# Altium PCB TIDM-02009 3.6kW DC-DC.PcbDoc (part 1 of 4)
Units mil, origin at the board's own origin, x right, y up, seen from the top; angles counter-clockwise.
Board outline 11220.47 x 8463 mil, 4 copper layers (Top Layer, Signal Layer 1, Signal Layer 2, Bottom Layer), stack 109.77 mil thick; 298 components, 250 nets, 959 pads, 2937 vias.
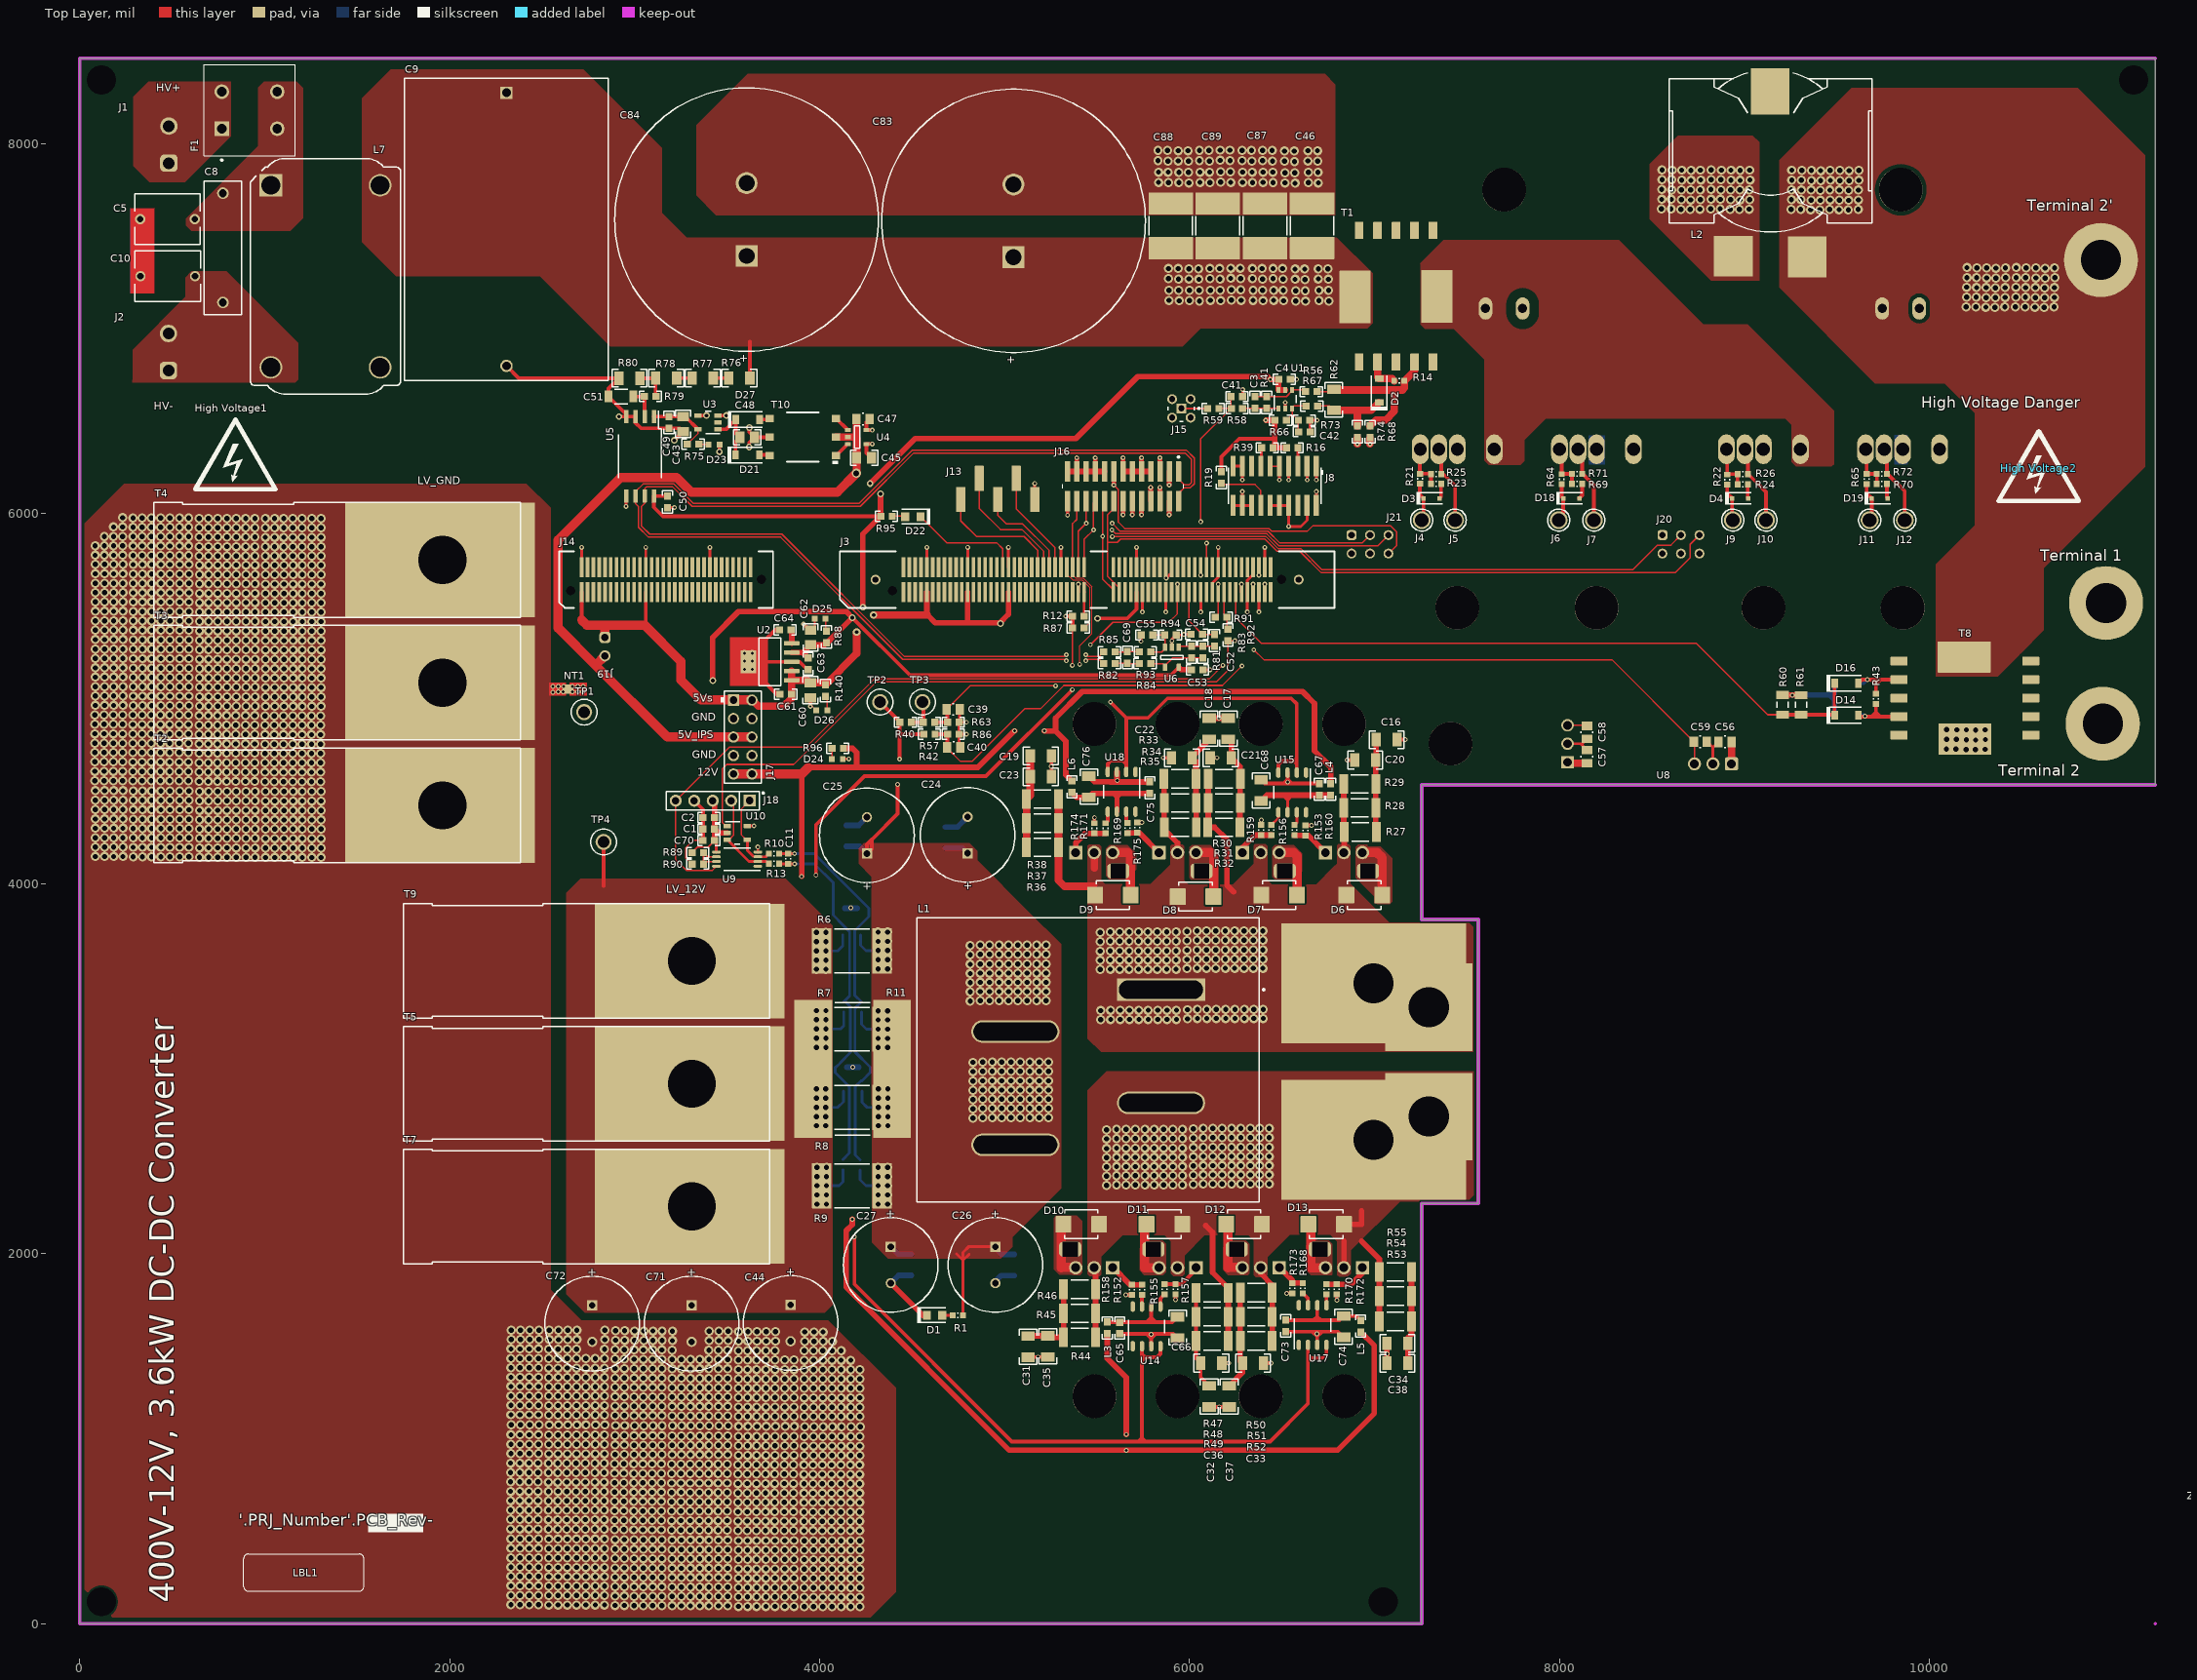
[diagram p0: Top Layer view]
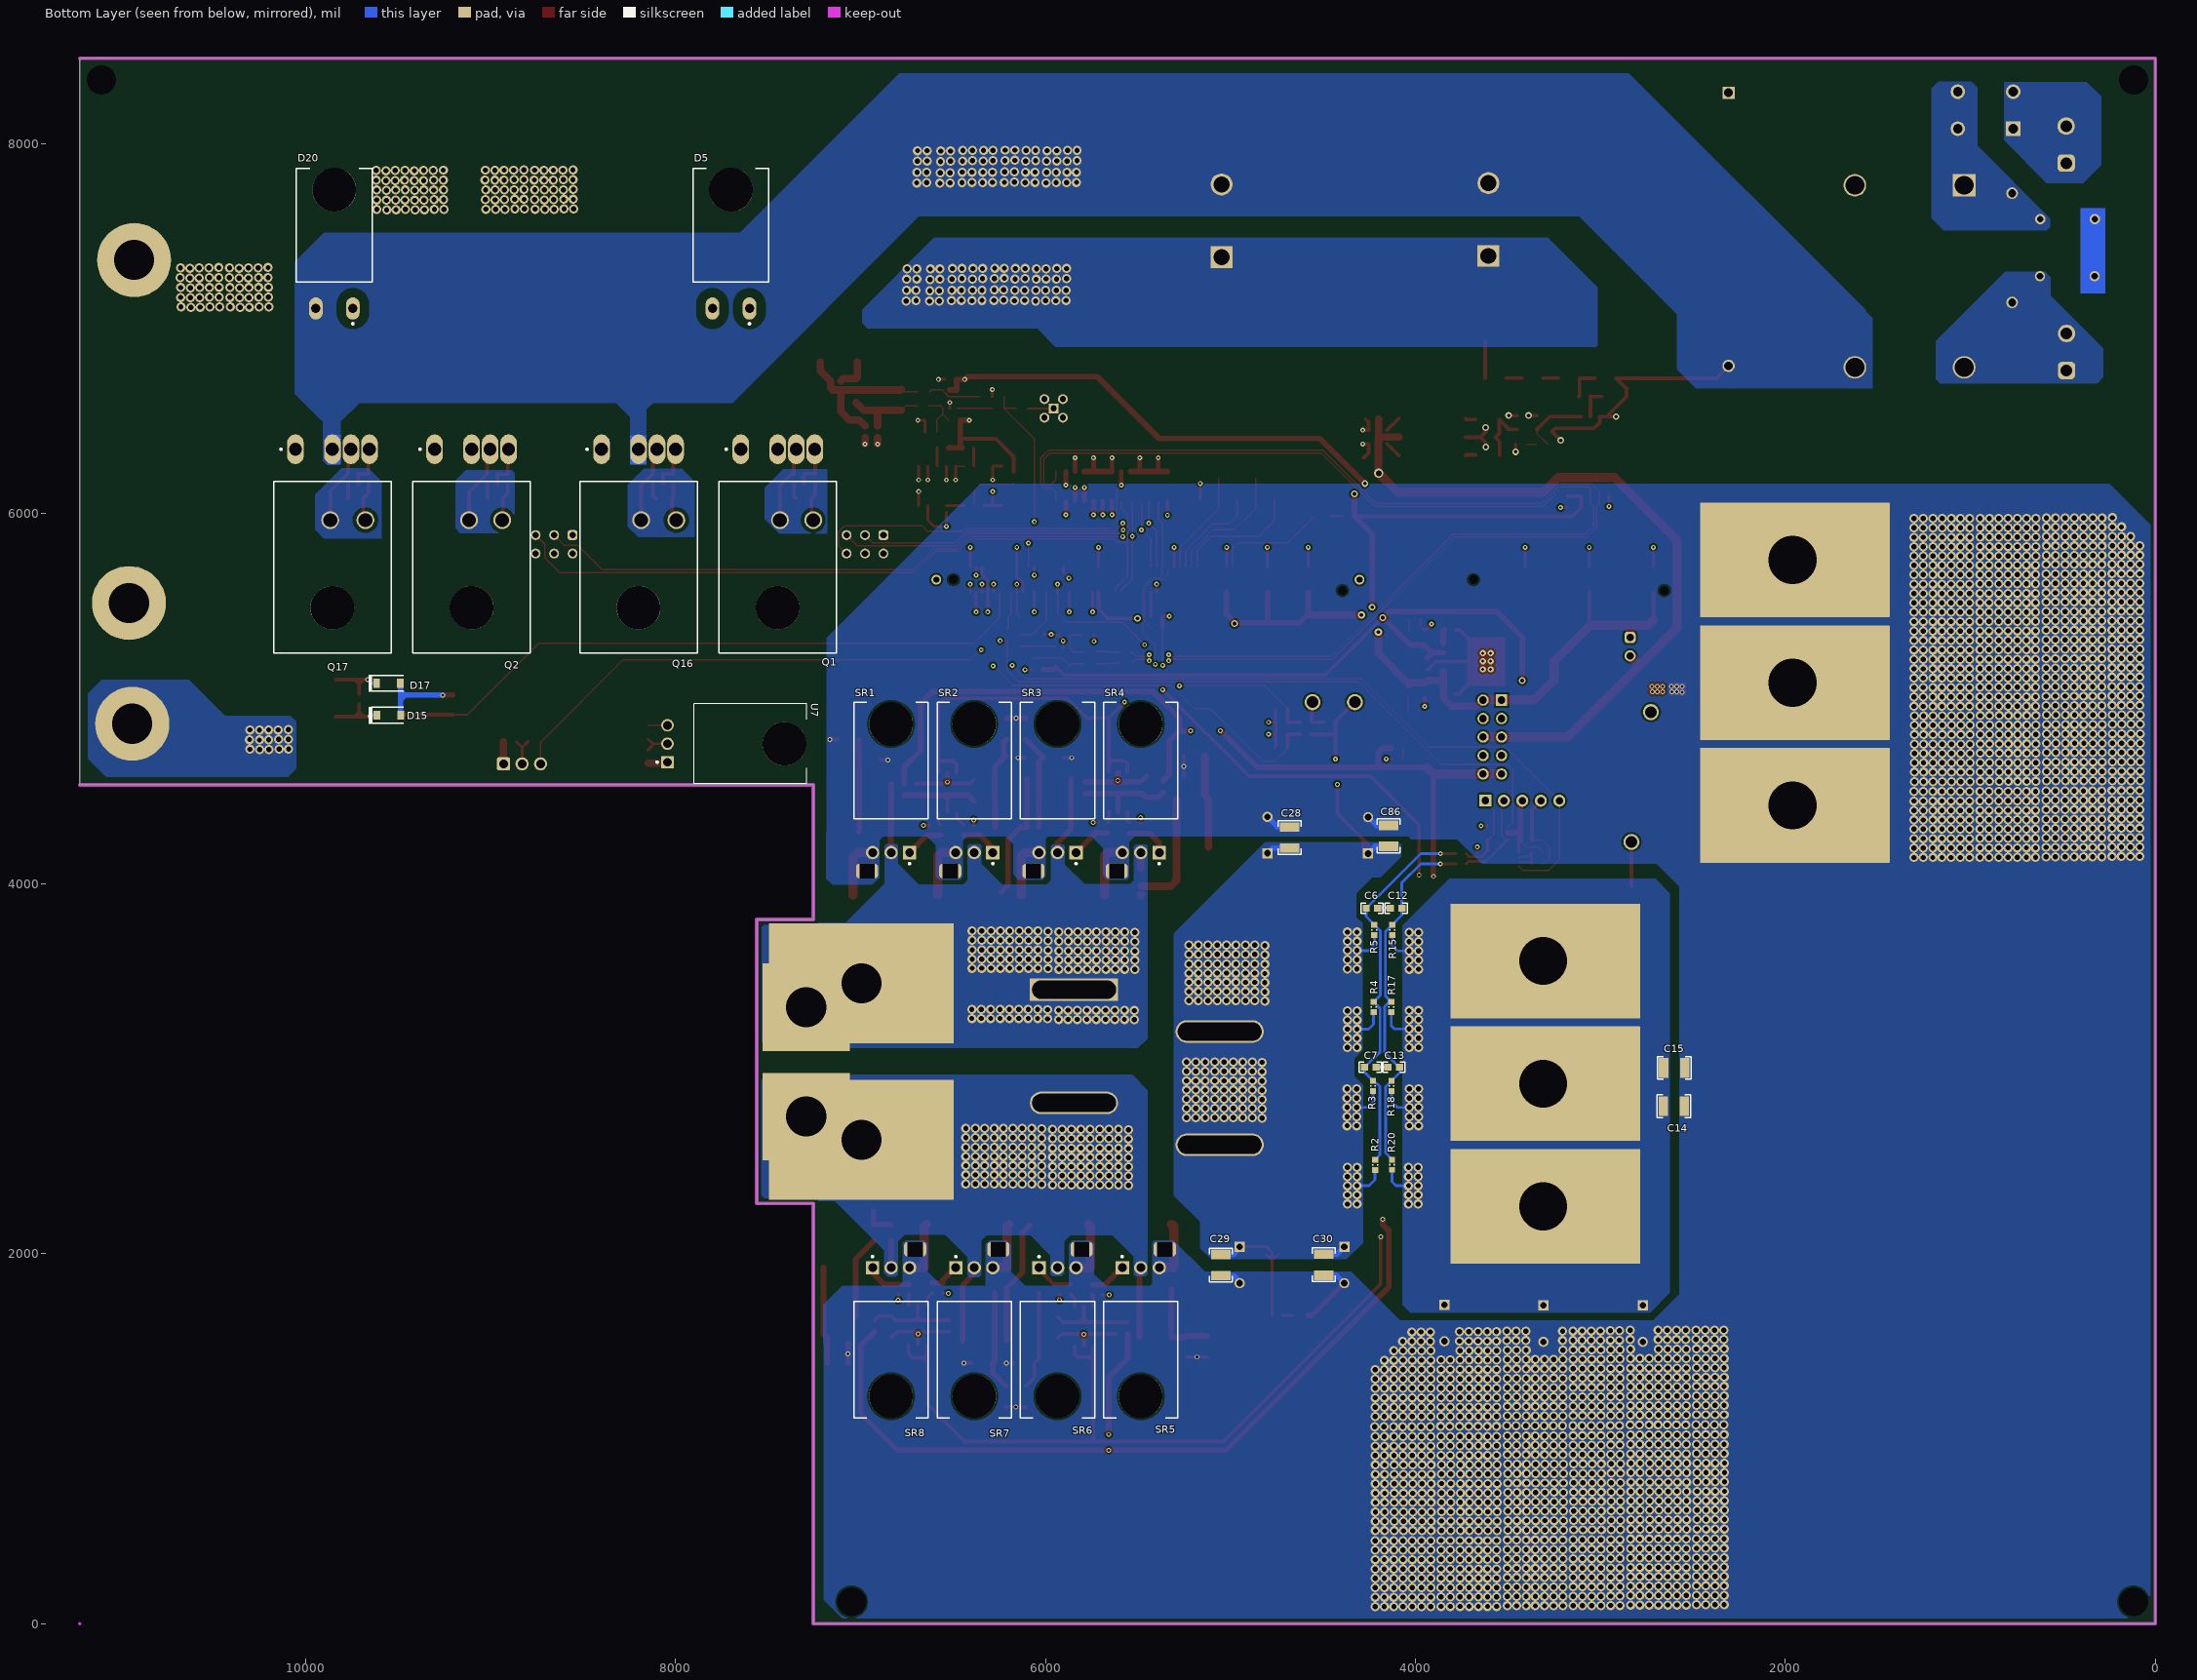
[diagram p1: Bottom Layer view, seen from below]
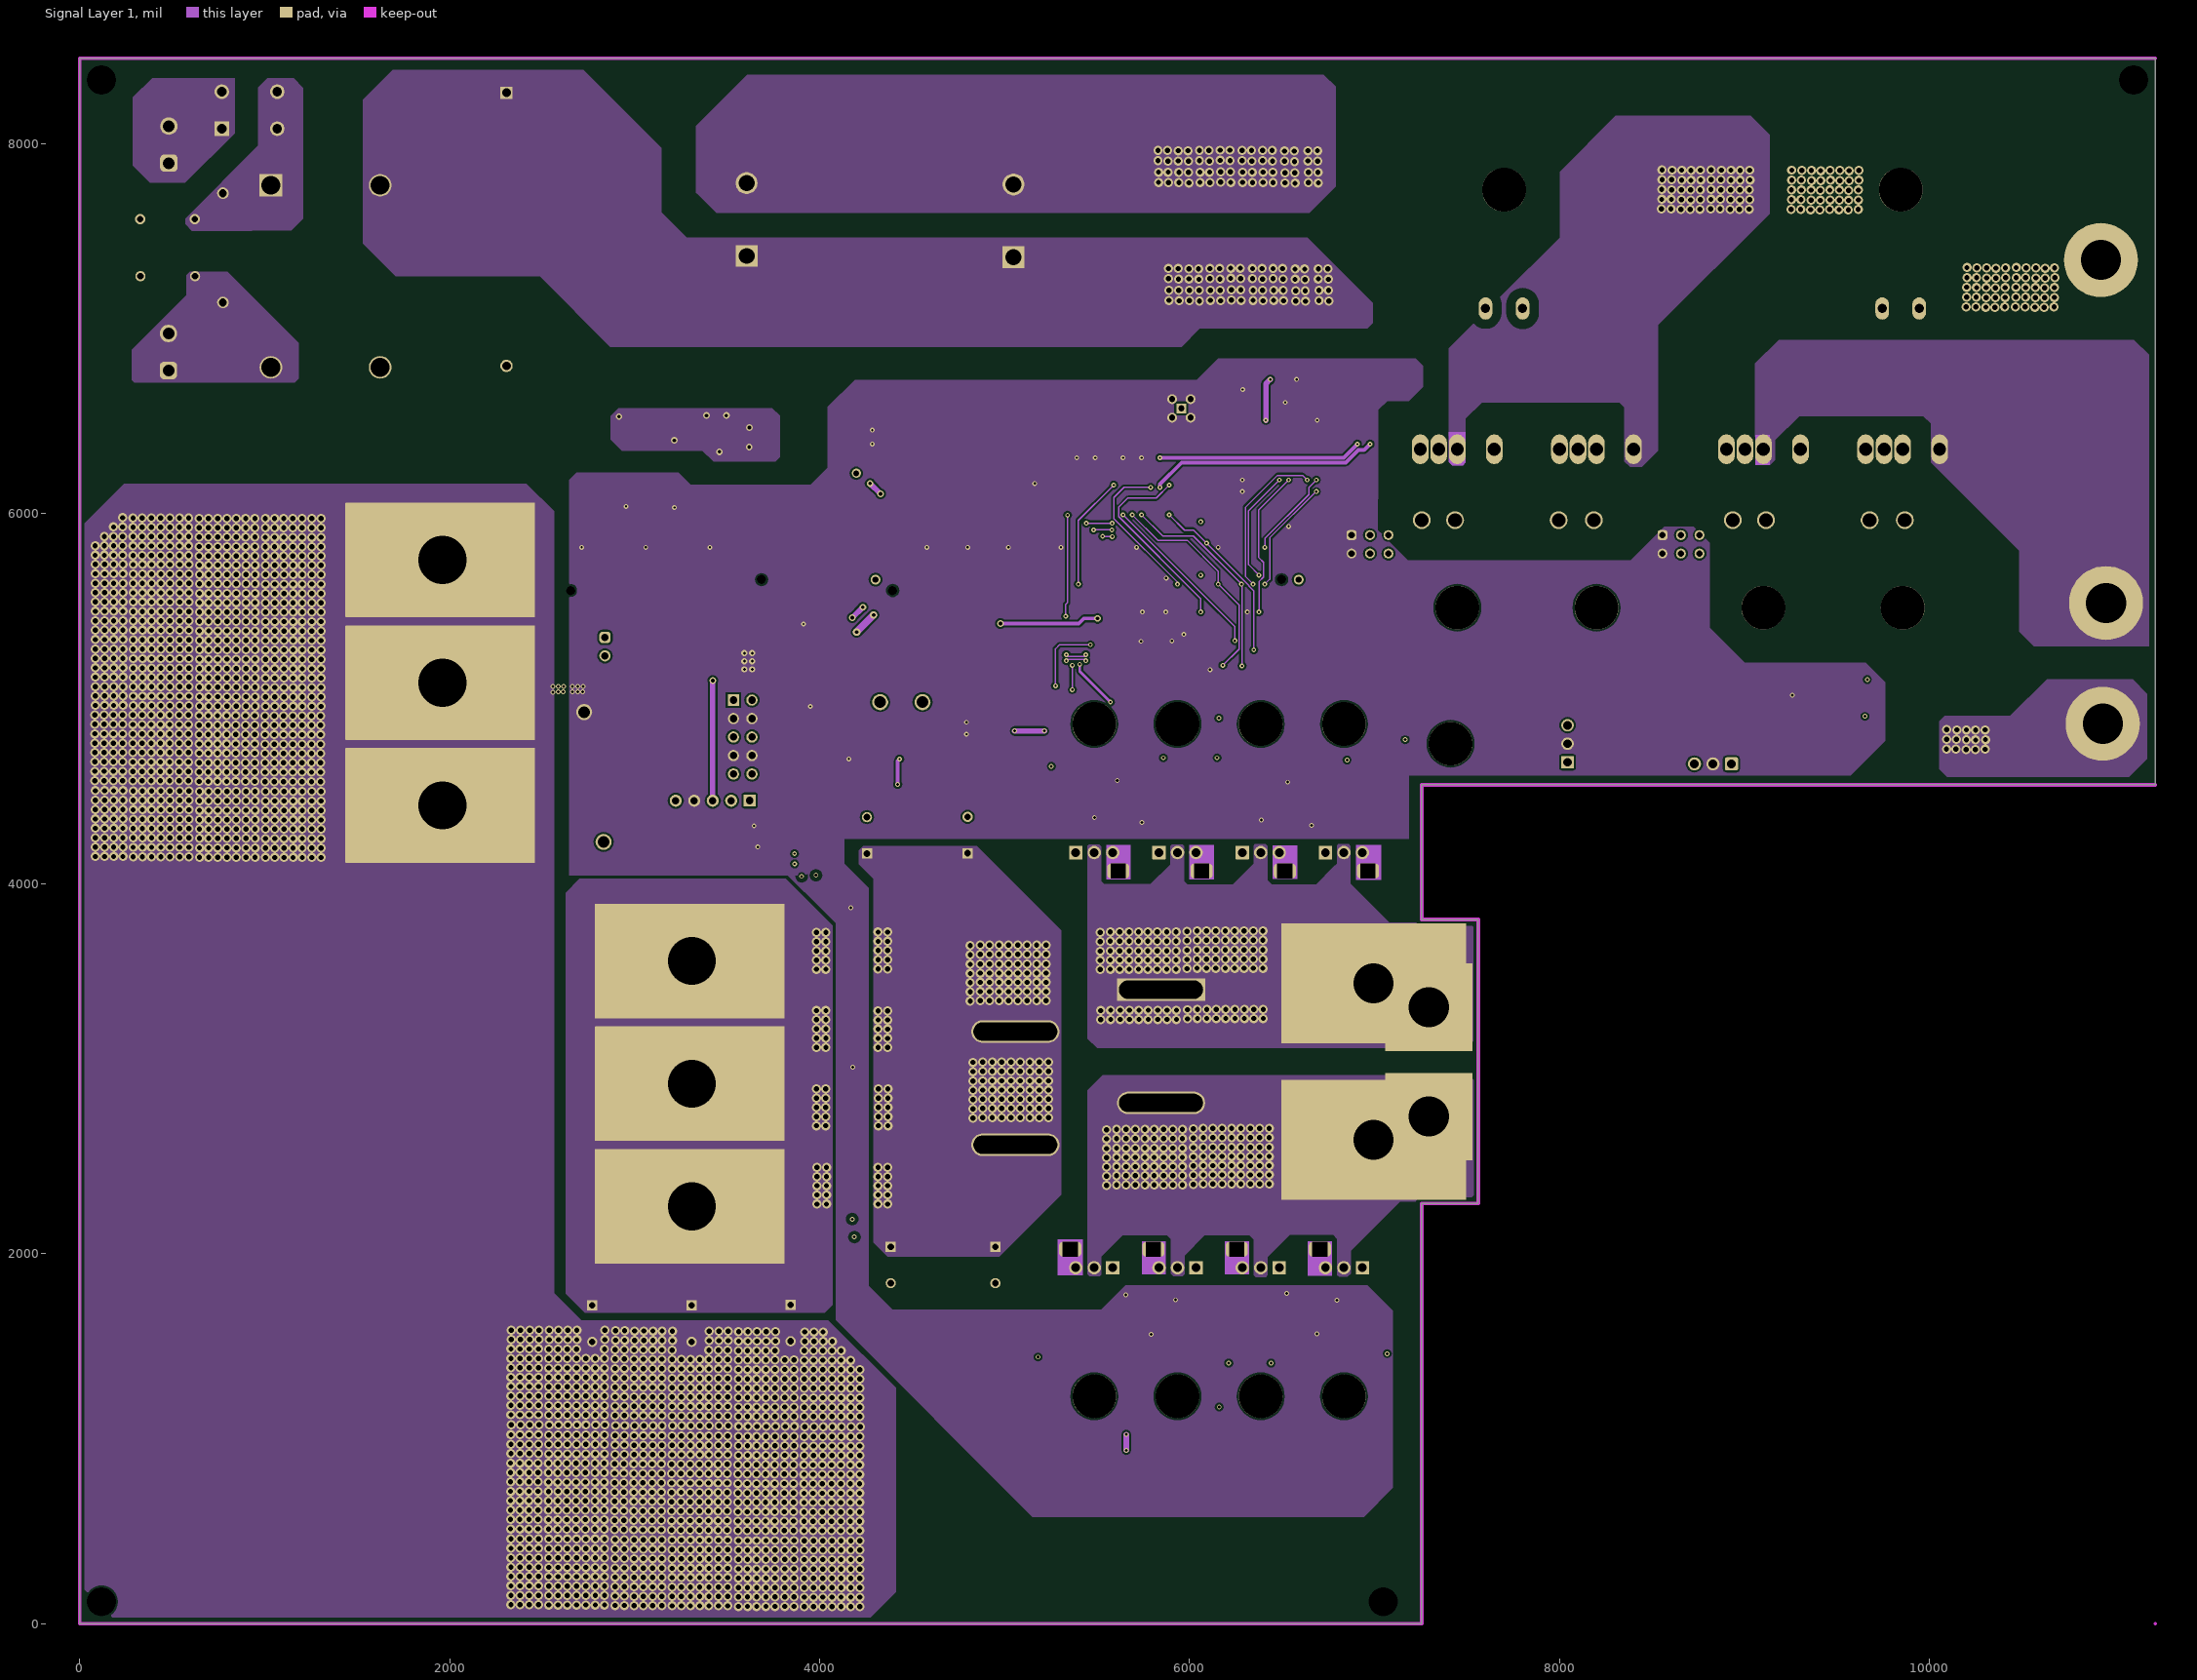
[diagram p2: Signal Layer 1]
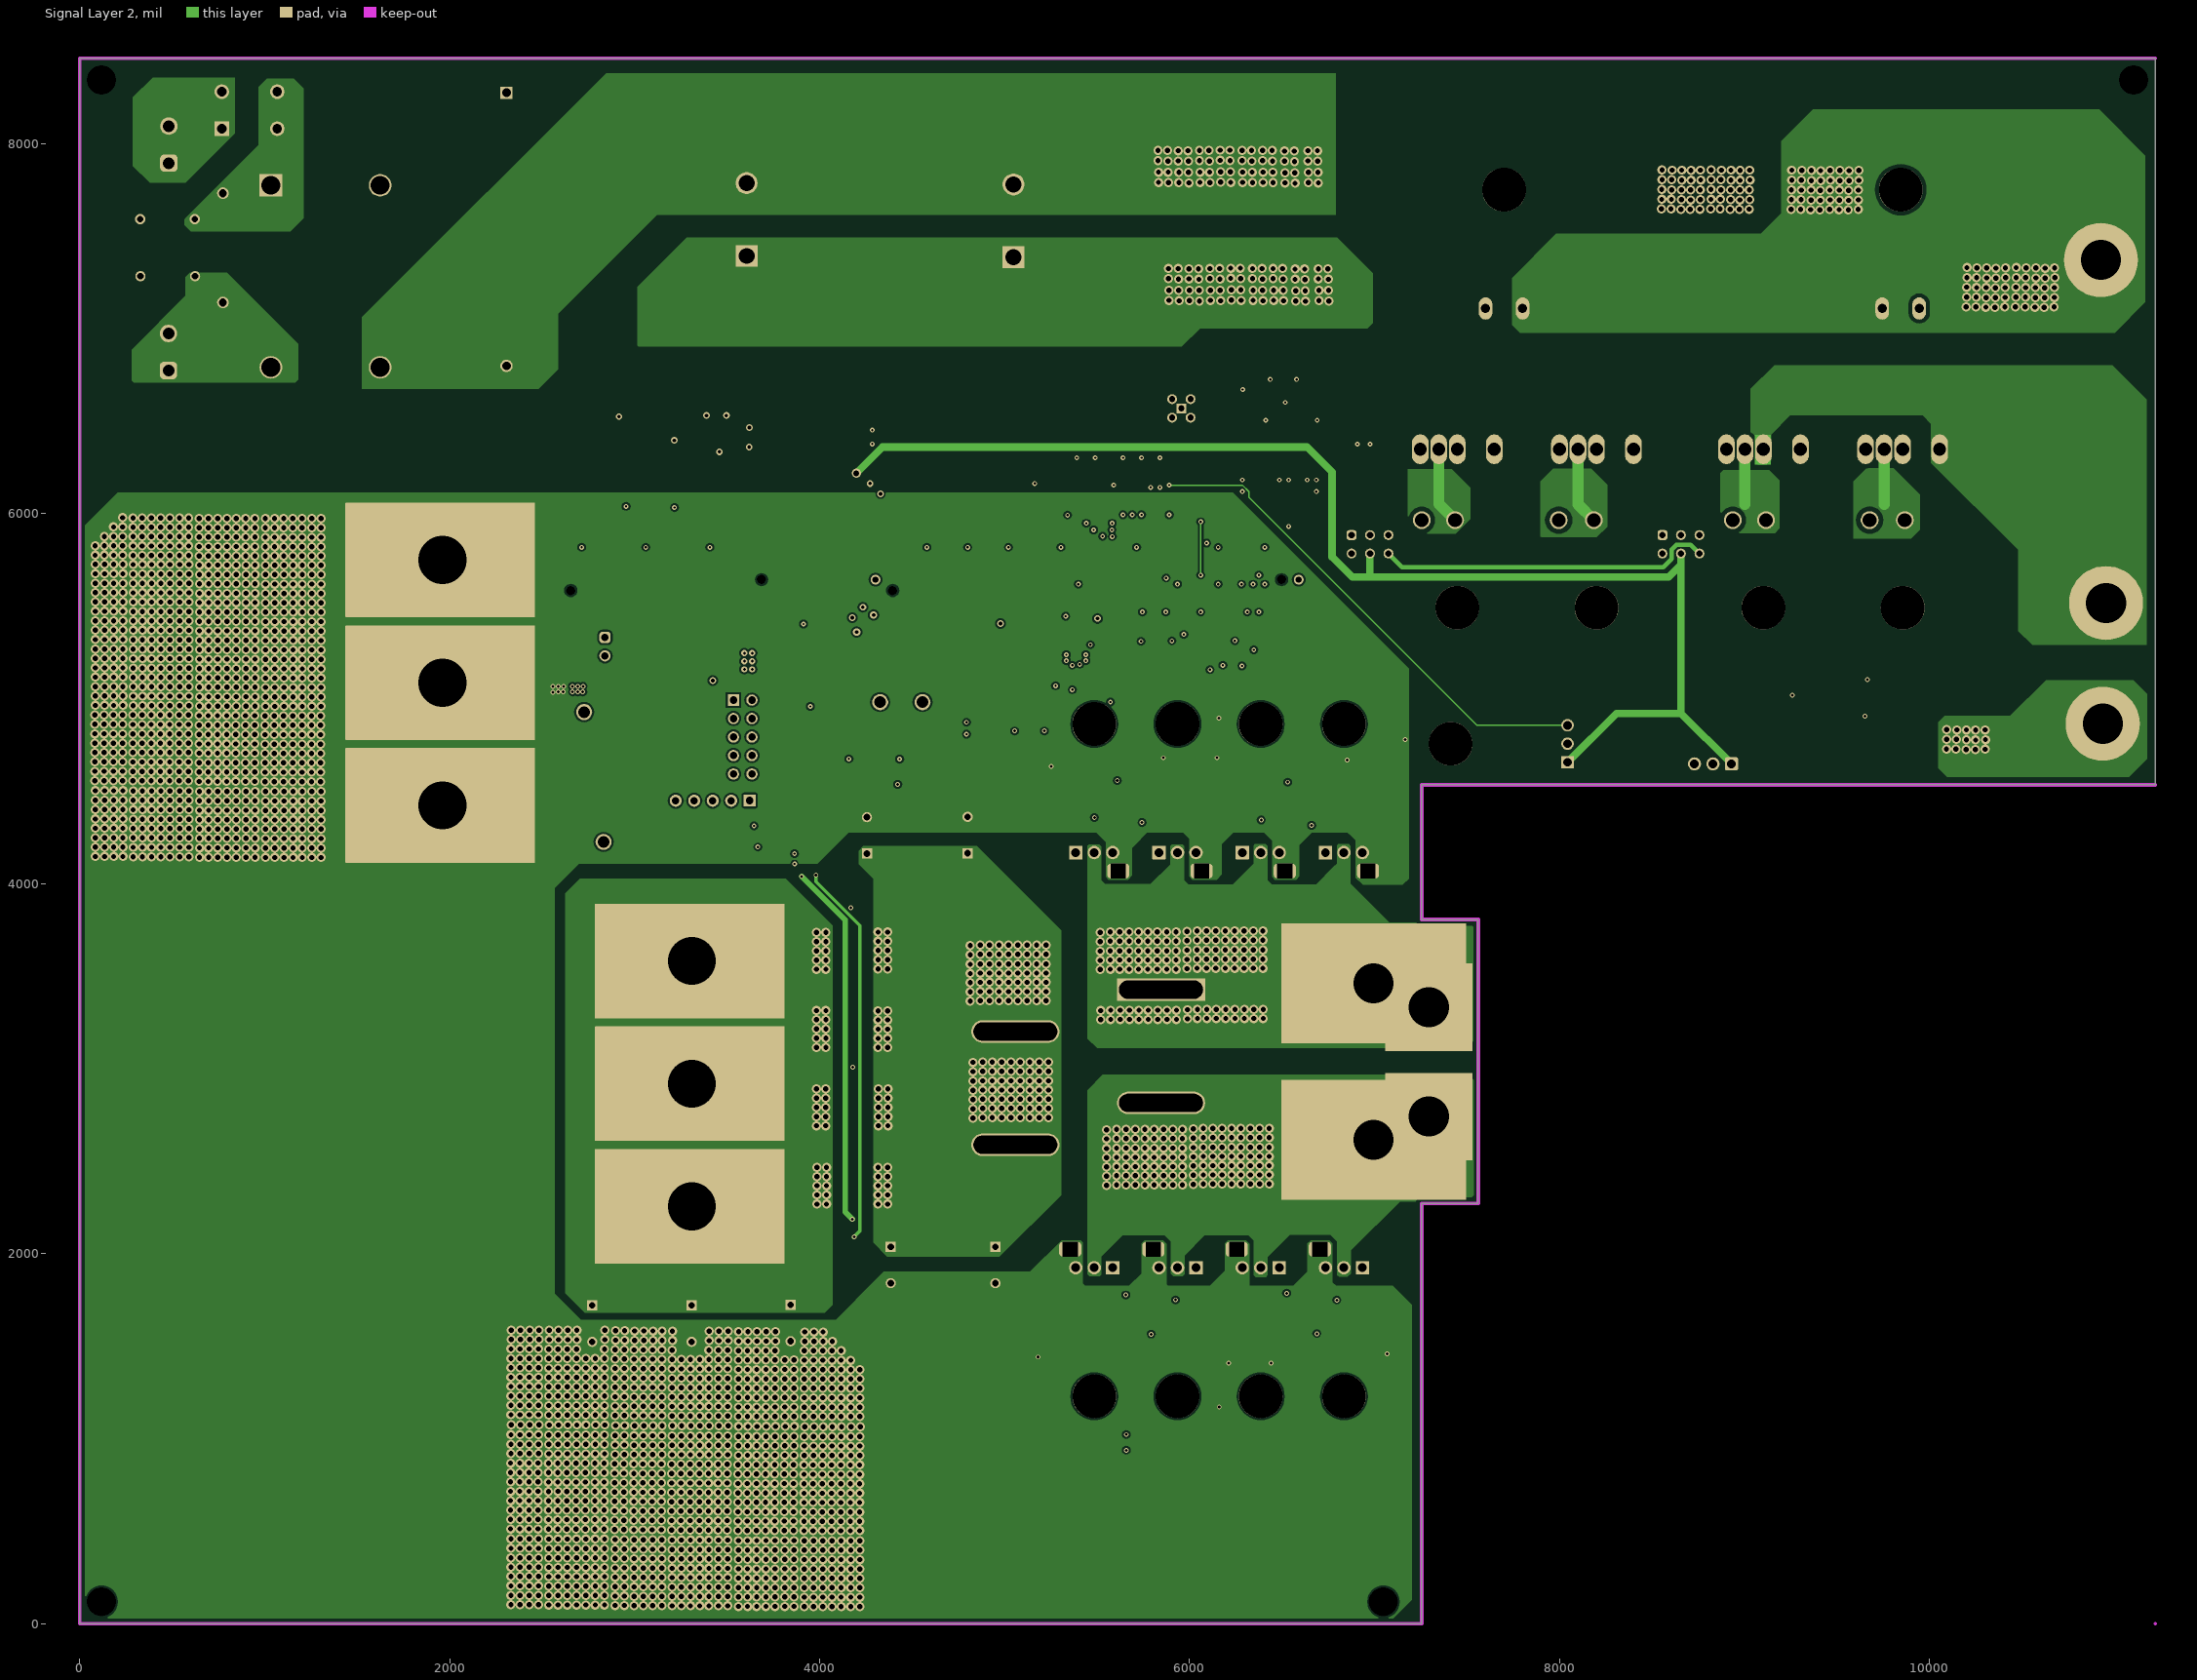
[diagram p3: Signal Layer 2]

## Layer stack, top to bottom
Top Solder: solder mask 0.4, Solder Resist, Dk 3.5
Top Layer: signal copper 2.8
Dielectric 2: dielectric 19.685, FR-4, Dk 4.2
Signal Layer 1: signal copper 2.8
Dielectric1: core 59.2, FR-4, Dk 4.8
Signal Layer 2: signal copper 2.8
Dielectric 3: dielectric 19.685, FR-4, Dk 4.2
Bottom Layer: signal copper 2.8
Bottom Solder: solder mask 0.4, Solder Resist, Dk 3.5

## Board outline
0,0 0,8463 11220.47,8463 11220.47,4534.85 7254.39,4534.85 7254.39,3806.5 7560,3806.5 7560,2271.07 7254.39,2271.07 7254.39,0

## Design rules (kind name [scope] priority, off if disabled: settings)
AcuteAngle [All] p1 off: minimum=4.50000000000000E+0001 checktracksonly=FALSE
AssemblyTestPointUsage [All] p1: valid=2
BoardOutlineClearance BoardOutlineClearance_MountingHoles [OnCopper and InComponentClass('Mounting Holes')] p1 off: gap=40 ignorepadtopadclearanceinfootprint=FALSE
BoardOutlineClearance BoardOutlineClearance_Poly [OnCopper and IsPoly] p2 off: gap=25 ignorepadtopadclearanceinfootprint=FALSE
BoardOutlineClearance [OnCopper and Not InComponentClass('Logo') and not InComponentClass('FiducialMark') and not InRegion(1000,500,4000,800) and not InPoly] p3 off: gap=75 ignorepadtopadclearanceinfootprint=FALSE
Clearance Clearance_D5_2 [(InNet('NetD5_2') AND IsPad)] p1: gap=50 ignorepadtopadclearanceinfootprint=FALSE
Clearance Clearance_Dbus+ [(InNet('Dbus+') AND IsPad AND OnLayer('Multi-Layer'))] p2: gap=50 ignorepadtopadclearanceinfootprint=FALSE
Clearance Clearance_Keepouts [((IsTrack Or IsArc) And Not InPoly) And IsFree and IsKeepOut vs ((IsTrack Or IsArc) And Not InPoly) And IsFree and IsKeepOut] p3: gap=0 ignorepadtopadclearanceinfootprint=FALSE
Clearance Clearance_Poly [InPolygon] p4: gap=10 ignorepadtopadclearanceinfootprint=FALSE
Clearance Clearance_FiducialMark [IsKeepOut and InComponentClass('FiducialMark') vs IsPad and InComponentClass('FiducialMark')] p5: gap=0 ignorepadtopadclearanceinfootprint=FALSE
Clearance [All] p6: gap=6 ignorepadtopadclearanceinfootprint=FALSE
ComponentClearance ComponentClearance_MountingHoles_FiducialMarks [InComponentClass('Mounting Holes') vs InComponentClass('FiducialMark')] p1: gap=50 collisioncheckmode=3 verticalgap=10 showdistances=FALSE
ComponentClearance ComponentClearance_Shunt [InComponentClass('Header') vs InComponentClass('Shunt')] p2: gap=0 collisioncheckmode=3 verticalgap=0 showdistances=FALSE
ComponentClearance ComponentClearance_Logo [InComponentClass('Logo')] p3: gap=50 collisioncheckmode=3 verticalgap=10 showdistances=FALSE
ComponentClearance ComponentClearance_ScrewToNut [(HasFootprint('NY PMS 440 0025 PH')) vs (HasFootprint('Keystone_1902C'))] p4: gap=5 collisioncheckmode=3 verticalgap=10 showdistances=FALSE
ComponentClearance ComponentClearance_MountingHoles [InComponentClass('Mounting Holes')] p5: gap=250 collisioncheckmode=3 verticalgap=100000 showdistances=FALSE
ComponentClearance ComponentClearance_SmallPassives [HasFootprint('0201*') or HasFootprint('0402*') or HasFootprint('0508') or HasFootprint('0603*') or HasFootprint('0612') or HasFootprint('0805*') or HasFootprint('0815*') or HasFootprint('0830*') or HasFootprint('1206*') or HasFootprint('1210*') or HasFootprint('1808*') or HasFootprint('1812*') or HasFootprint('1825*') or HasFootprint('2010*') or HasFootprint('2220*') or HasFootprint('2225*') or HasFootprint('2512*') or HasFootprint('2728*') or HasFootprint('3518*') vs HasFootprint('0201*') or HasFootprint('0402*') or HasFootprint('0508') or HasFootprint('0603*') or HasFootprint('0612') or HasFootprint('0805*') or HasFootprint('0815*') or HasFootprint('0830*') or HasFootprint('1206*') or HasFootprint('1210*') or HasFootprint('1808*') or HasFootprint('1812*') or HasFootprint('1825*') or HasFootprint('2010*') or HasFootprint('2220*') or HasFootprint('2225*') or HasFootprint('2512*') or HasFootprint('2728*') or HasFootprint('3518*')] p6: gap=14.96 collisioncheckmode=3 verticalgap=10 showdistances=FALSE
ComponentClearance ComponentClearance_THtoSMT [IsThruComponent vs IsSMTComponent] p7 off: gap=40 collisioncheckmode=3 verticalgap=30 showdistances=FALSE
ComponentClearance ComponentClearance_THtoTH [IsThruComponent vs IsThruComponent] p8 off: gap=30 collisioncheckmode=3 verticalgap=30 showdistances=FALSE
ComponentClearance [InComponent('No Component') vs InComponent('No Component')] p9: gap=30 collisioncheckmode=3 verticalgap=10 showdistances=FALSE
DiffPairsRouting [All] p1: maxlimit=100 minlimit=6 mostfreqgap=8 toplayer_minwidth=6 toplayer_maxwidth=15 toplayer_prefwidth=8 midlayer1_minwidth=6 midlayer1_maxwidth=15 midlayer1_prefwidth=8 midlayer2_minwidth=6 midlayer2_maxwidth=15 midlayer2_prefwidth=8 bottomlayer_minwidth=6 bottomlayer_maxwidth=15 bottomlayer_prefwidth=8 maxuncoupledlength=1000
FabricationTestPointUsage TestPointUsage [All] p1: valid=2 allowmultiple=FALSE
FabricationTestpoint Testpoint [All] p1: side=3 testpointundercomponent=TRUE minsize=40 maxsize=100 preferedsize=60 minholesize=0 maxholesize=40 preferedholesize=32 testpointgrid=1 allowsidetop=TRUE allowsidebottom=TRUE usegrid=TRUE gridtolerance=0.01
FanoutControl Fanout_LCC [IsLCC] p1: bgadir=Out bgaviamode=Centered fanoutstyle=Auto fanoutdirection=Alternating viagrid=1 // Fanout_LCC (Default Rule)
FanoutControl Fanout_BGA [IsBGA] p2: bgadir=Out bgaviamode=Centered fanoutstyle=Auto fanoutdirection=Alternating viagrid=1 // Fanout_BGA (Default Rule)
FanoutControl Fanout_Default [All] p4: bgadir=Out bgaviamode=Centered fanoutstyle=Auto fanoutdirection=Alternating viagrid=1 // Fanout_Default (Default Rule)
FanoutControl Fanout_Small [(CompPinCount < 5)] p5: bgadir=Out bgaviamode=Centered fanoutstyle=Auto fanoutdirection=OutThenIn viagrid=1 // Fanout_Small (Default Rule)
Height [All] p1 off: minheight=0 maxheight=1000 prefheight=500
HoleSize [All] p1: absolutevalues=TRUE maxlimit=1000 minlimit=7.87 maxpercent=80.000 minpercent=20.000
MinimumAnnularRing MinimumAnnularRing_ThermalPadVias [IsVia and InAnyComponent] p1: minimumring=5.91
MinimumAnnularRing [All] p2: minimumring=4
MinimumSolderMaskSliver MinimumSolderMaskSliver_Logo [InComponentClass('Logo') vs InComponentClass('Logo')] p1 off: minsoldermaskwidth=0.7
MinimumSolderMaskSliver [All] p2 off: minsoldermaskwidth=3.94
PlaneClearance [All] p1: clearance=15
PlaneConnect [All] p1: planeconnectstyle=Relief reliefexpansion=10 reliefentries=4 reliefconductorwidth=10 reliefairgap=10
PolygonConnect [All] p1: connectstyle=Direct reliefconductorwidth=10 reliefentries=4 polygonreliefangle="90 Angle" airgapwidth=10
RoutingVias ThermalPadVias [IsVia and InAnyComponent] p1: holewidth=7.87 width=19.68 viastyle="Through Hole" minholewidth=7.87 minwidth=19.68 maxholewidth=12.99 maxwidth=23.62
RoutingVias [All] p2: holewidth=16 width=34 viastyle="Through Hole" minholewidth=7.87 minwidth=26 maxholewidth=100 maxwidth=100
SilkToBoardRegionClearance [Not ((IsComment or IsDesignator) And (Hide <> 'False')) and not InRegion(1000,500,4000,800)] p1:
SilkToSilkClearance SilkToSilkClearance_Pb-FreeLogo [(HasFootprint('Pb-Free_Overlay_Medium') OR HasFootprint('Pb-Free_Overlay_Small')) vs (HasFootprint('Pb-Free_Overlay_Medium') OR HasFootprint('Pb-Free_Overlay_Small'))] p1 off: silktosilkclearance=0
SilkToSilkClearance [All] p2 off: silktosilkclearance=4
SilkToSolderMaskClearance SilkToComponentPadClearance [(IsPad or IsFill or IsRegion) and InAnycomponent] p1 off: minsilkscreentomaskgap=5 clearancetoexposedcopper=TRUE
SilkToSolderMaskClearance "Silk to Solder Mask Opening" [All] p2 off: minsilkscreentomaskgap=4 clearancetoexposedcopper=FALSE
SolderMaskExpansion [All] p1: expansion=1.97 istentingtop=FALSE
Width Width_12V [InNet('+12V')] p1: maxlimit=100 minlimit=30 preferedwidth=30 minimp=50.000000 maximp=50.000000 favimp=50.000000
Width Width_1 [All] p2 off: maxlimit=100 minlimit=6 preferedwidth=8
Width Width_5V [InNet('5Vs')] p3: maxlimit=100 minlimit=20 preferedwidth=30 minimp=50.000000 maximp=50.000000 favimp=50.000000
13 further rules are at their usual default settings.

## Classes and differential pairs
component class Label: LBL1
component class TIDM-02009_DCDC_C2000: D22 J3 J8 J13 J14 R12 R16 R19 R39 R87 R91 R92 R95
component class "TIDM-02009_DCDC_Power Stage": C1 C2 C5 C6 C7 C8 C9 C10 C11 C12 C13 C14 C15 C16 C17 C18 C19 C20 C21 C22 C23 C24 C25 C26 C27 C28 C29 C30 C31 C32 C33 C34 C35 C36 C37 C38 C44 C46 C70 C71 C72 C83 C84 C86 C87 C88 C89 D1 D3 D4 D5 D6 D7 D8 D9 D10 D11 D12 D13 D14 D15 D16 D17 D18 D19 D20 F1 J1 J2 J4 J5 J6 J7 J9 J10 J11 J12 J18 L1 L2 L7 NT1 Q1 Q2 Q16 Q17 R1 R2 R3 R4 R5 R6 R7 R8 R9 R10 R11 R13 R14 R15 R17 R18 R20 R21 R22 R23 R24 R25 R26 R27 R28 R29 R30 R31 R32 R33 R34 R35 R36 R37 R38 R43 R44 R45 R46 R47 R48 R49 R50 R51 R52 R53 R54 R55 R60 R61 R64 R65 R69 R70 R71 R72 R89 R90 SR1 SR2 SR3 SR4 SR5 SR6 SR7 SR8 T1 T2 T3 T4 T5 T7 T8 T9 TP1 TP4 U9 U10
component class TIDM-02009_DCDC_Control: C3 C4 C39 C40 C41 C42 C43 C45 C47 C48 C49 C50 C51 C52 C53 C54 C55 C56 C57 C58 C59 C60 C61 C62 C63 C64 C65 C66 C67 C68 C69 C73 C74 C75 C76 D2 D21 D23 D24 D25 D26 D27 J15 J16 J17 J19 J20 J21 L3 L4 L5 L6 R40 R41 R42 R56 R57 R58 R59 R62 R63 R66 R67 R68 R73 R74 R75 R76 R77 R78 R79 R80 R81 R82 R83 R84 R85 R86 R88 R93 R94 R96 R140 R152 R153 R155 R156 R157 R158 R159 R160 R168 R169 R170 R171 R172 R173 R174 R175 T10 TP2 TP3 U1 U2 U3 U4 U5 U6 U7 U8 U14 U15 U17 U18
component class Header: J8 J13 J17 J18 J19
component class TIDM-02009_DCDC_Hardware: "High Voltage1" "High Voltage2" LBL1 ZZ1 ZZ2 ZZ3 ZZ4
component class AssemblyNote: ZZ1 ZZ2 ZZ3 ZZ4
differential pair VIN: +VIN_P -VIN_N

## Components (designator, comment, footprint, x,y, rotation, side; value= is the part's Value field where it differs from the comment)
C1 "GRM188R72A104KA35D" 0603 3401,4296 r180 top value=0.1uF
C2 "GRM188R71E105KA12D" 0603 3401,4358 r180 top value=1uF
C3 "GRM188R72A221KA01D" 0603 6354,6602.5 r90 top value=220pF
C4 "GRM188R72A104KA35D" 0603 6512,6726.5 r0 top value=0.1uF
C5 "DE6E3KJ222MN3A" E_900x700x900 474.59,7592.97 r180 top value=2200pF
C6 "06035A101JAT2A" 0603 4234.55,3868 r180 bottom value=100pF
C7 "06035A101JAT2A" 0603 4243.05,3008 r180 bottom value=100pF
C8 "R73PI21004000J" R73_1800x500x1100 774,7438 r270 top value=0.01uF
C9 "B32926C3106K" B32926_42.5mm 2307,7538 r270 top value=10uF
C10 "DE6E3KJ222MN3A" E_900x700x900 476,7285 r0 top value=2200pF
C11 "GRM188R71E105KA12D" 0603L 3830,4135 r270 top value=1uF
C12 "06035A101JAT2A" 0603 4104.55,3868 r0 bottom value=100pF
C13 "06035A101JAT2A" 0603 4116.04,3008 r0 bottom value=100pF
C14 "GRM32ER7YA106KA12K" 1210_270 2603,2798.25 r180 bottom value=10uF
C15 "GRM32ER7YA106KA12K" 1210_270 2601,3004.25 r180 bottom value=10uF
C16 "12061C152KAT2A" 1206 7065.12,4778.79 r180 top value=1500pF
C17 "12061C152KAT2A" 1206 6209,4838 r270 top value=1500pF
C18 "12061C152KAT2A" 1206 6105,4838 r270 top value=1500pF
C19 "12061C152KAT2A" 1206 5195.61,4691.2 r180 top value=1500pF
C20 "12061C152KAT2A" 1206 6949.31,4668.79 r0 top value=1500pF
C21 "12061C152KAT2A" 1206 6168.42,4680.79 r0 top value=1500pF
C22 "12061C152KAT2A" 1206 5958.39,4680.79 r0 top value=1500pF
C23 "12061C152KAT2A" 1206 5195.61,4578.72 r180 top value=1500pF
C24 "B41896C7397M000" B41896_1250x2000 4800.06,4263.37 r90 top value=390uF
C25 "B41896C7397M000" B41896_1250x2000 4255.61,4261.66 r90 top value=390uF
C26 "B41896C7397M000" B41896_1250x2000 4950,1939 r270 top value=390uF
C27 "B41896C7397M000" B41896_1250x2000 4384.39,1939.11 r270 top value=390uF
C28 "GRM32ER7YA106KA12K" 1210_270 4680,4249.91 r90 bottom value=10uF
C29 "GRM32ER7YA106KA12K" 1210_270 5052,1939 r270 bottom value=10uF
C30 "GRM32ER7YA106KA12K" 1210_270 4496,1940 r270 bottom value=10uF
C31 "12061C152KAT2A" 1206 5126.52,1497.35 r90 top value=1500pF
C32 "12061C152KAT2A" 1206 6105.73,1228.23 r90 top value=1500pF
C33 "12061C152KAT2A" 1206 6342.78,1408.23 r180 top value=1500pF
C34 "12061C152KAT2A" 1206 7123.13,1514.69 r0 top value=1500pF
C35 "12061C152KAT2A" 1206 5233.52,1498.44 r90 top value=1500pF
C36 "12061C152KAT2A" 1206 6117,1408.23 r180 top value=1500pF
C37 "12061C152KAT2A" 1206 6213.91,1228.23 r90 top value=1500pF
C38 "12061C152KAT2A" 1206 7123.13,1407.69 r0 top value=1500pF
C39 "CEU4J2X7R1H104K125AE" 0805_150 4721.57,4943 r0 top value=0.1uF
C40 "CEU4J2X7R1H104K125AE" 0805_150 4724,4737 r0 top value=0.1uF
C41 "GRM188R72A221KA01D" 0603 6255.5,6633.5 r0 top value=220pF
C42 "GRM188R72A221KA01D" 0603 6620,6443.5 r0 top value=220pF
C43 "CL21B106KOQNNNE" 0805_HV 3262,6485 r270 top value=10uF
C44 "B41896C7397M000" B41896_1250x2000 3843,1625 r270 top value=390uF
C45 "CL21B106KOQNNNE" 0805_HV 4240,6303 r0 top value=10uF
C46 "2220Y6300105KXTWS2" 2220_450 6662,7557 r90 top value=1uF
C47 "CEU4J2X7R1H104K125AE" 0805_150 4234,6512 r0 top value=0.1uF
C48 "CL21B106KOQNNNE" 0805_HV 3608,6414 r0 top value=10uF
C49 "GRM188R72A104KA35D" 0603 3185,6494 r270 top value=0.1uF
C50 "GRM188R72A104KA35D" 0603 3178,6065 r270 top value=0.1uF
C51 "C3216X7R2A334K130AA" 1206_150 2926,6634 r180 top value=0.33uF
C52 "C0603X221K5RACTU" 0603 6072,5252 r270 top value=220pF
C53 "GRM188R72A104KA35D" 0603 6042,5157 r0 top value=0.1uF
C54 "C0603X221K5RACTU" 0603 6039,5348 r180 top value=220pF
C55 "C0603X221K5RACTU" 0603 5769,5345 r180 top value=220pF
C56 "CEU4J2X7R1H104K125AE" 0805_150 8894,4767 r180 top value=0.1uF
C57 "CEU4J2X7R1H104K125AE" 0805_150 8148,4687 r90 top value=0.1uF
C58 "CEU4J2X7R1H104K125AE" 0805_150 8148,4818 r270 top value=0.1uF
C59 "CEU4J2X7R1H104K125AE" 0805_150 8761,4768 r0 top value=0.1uF
C60 "CL21B106KOQNNNE" 0805_HV 3950,5046 r270 top value=10uF
C61 "GRM188R72A104KA35D" 0603 3816.5,5025 r180 top value=0.1uF
C62 "CL21B106KOQNNNE" 0805_HV 3951,5331 r90 top value=10uF
C63 "GRM188R72A104KA35D" 0603 3938,5189 r270 top value=0.1uF
C64 "GCM188R71H103KA37D" 0603 3813,5372 r180 top value=0.01uF
C65 "CGA3E2X7R1E104K080AA" 0603 5622.23,1598.2 r270 top value=0.1uF
C66 "GRM319R61H475KA12" 1206 5934.75,1601.17 r270 top value=4.7uF
C67 "CGA3E2X7R1E104K080AA" 0603 6701.41,4510.28 r90 top value=0.1uF
C68 "GRM319R61H475KA12" 1206 6386.88,4504.33 r90 top value=4.7uF
C69 "GRM188R72A104KA35D" 0603 5664,5223 r90 top value=0.1uF
C70 "GRM188R72A104KA35D" 0603 3401,4234 r180 top value=0.1uF
C71 "B41896C7397M000" B41896_1250x2000 3308,1622 r270 top value=390uF
C72 "B41896C7397M000" B41896_1250x2000 2771,1622 r270 top value=390uF
C73 "CGA3E2X7R1E104K080AA" 0603 6519.52,1609.44 r270 top value=0.1uF
C74 "GRM319R61H475KA12" 1206 6832.52,1605.44 r270 top value=4.7uF
C75 "CGA3E2X7R1E104K080AA" 0603 5785.22,4518.95 r90 top value=0.1uF
C76 "GRM319R61H475KA12" 1206 5455.22,4524.54 r90 top value=4.7uF
C83 "LGN2X121MELC35" Nichicon_3500x3500_Snap 5048,7583.85 r90 top value=120uF
C84 "LGN2X121MELC35" Nichicon_3500x3500_Snap 3605,7590.85 r90 top value=120uF
C86 "GRM32ER7YA106KA12K" 1210_270 4144,4258.91 r90 bottom value=10uF
C87 "2220Y6300105KXTWS2" 2220_450 6407.33,7557 r90 top value=1uF
C88 "2220Y6300105KXTWS2" 2220_450 5898,7557 r90 top value=1uF
C89 "2220Y6300105KXTWS2" 2220_450 6152.67,7557 r90 top value=1uF
D1 "150080SS75000" WL-SMCW_RED_0805 4621.66,1667 r0 top value=Red
D2 "1N4148W-7-F" SOD-123 7025,6666.53 r90 top value=100V
D3 "CUS05S40,H3F" SOD-323 7307,6084 r0 top value=40V
D4 "CUS05S40,H3F" SOD-323 8976.31,6084 r0 top value=40V
D5 "C6D10065A" FP-C6D10065A_TO-220-2-Recommended_Land_Pattern_Horizontal 7700,7561 r180 bottom
D6 "TPSMB51CA" FP-TPSMB51CA_DO214AA-MFG 6944.06,3938.79 r0 top
D7 "TPSMB51CA" FP-TPSMB51CA_DO214AA-MFG 6484.39,3938.79 r0 top
D8 "TPSMB51CA" FP-TPSMB51CA_DO214AA-MFG 6032,3930 r0 top
D9 "TPSMB51CA" FP-TPSMB51CA_DO214AA-MFG 5584.58,3938.79 r0 top
D10 "TPSMB51CA" FP-TPSMB51CA_DO214AA-MFG 5414.58,2158.79 r0 top
D11 "TPSMB51CA" FP-TPSMB51CA_DO214AA-MFG 5863.41,2158.79 r0 top
D12 "TPSMB51CA" FP-TPSMB51CA_DO214AA-MFG 6294.39,2158.79 r0 top
D13 "TPSMB51CA" FP-TPSMB51CA_DO214AA-MFG 6738.22,2158.79 r0 top
D14 "IN4148" SOD-123 9551,4911 r0 top value=100V
D15 "IN4148" SOD-123 9550,4911 r180 bottom value=100V
D16 "IN4148" SOD-123 9551,5084 r0 top value=100V
D17 "IN4148" SOD-123 9551,5084 r180 bottom value=100V
D18 "CUS05S40,H3F" SOD-323 8063,6084 r0 top value=40V
D19 "CUS05S40,H3F" SOD-323 9730.31,6084 r0 top value=40V
D20 "C6D10065A" FP-C6D10065A_TO-220-2-Recommended_Land_Pattern_Horizontal 9844,7561 r180 bottom
D21 "MBR0540T1G" SOD-123 3610,6318 r0 top value=40V
D22 "150080SS75000" WL-SMCW_RED_0805 4503.66,5985 r180 top value=Red
D23 "LTST-C193KGKT-5A" LTST-C193_Green 3428.78,6374 r0 top value=Green
D24 "LTST-C193KGKT-5A" LTST-C193_Green 4095.47,4675 r0 top value=Green
D25 "LTST-C193KGKT-5A" LTST-C193_Green 4003,5433 r180 top value=Green
D26 "LTST-C193KGKT-5A" LTST-C193_Green 4012,4937 r180 top value=Green
D27 "MBR0540T1G" SOD-123 3611,6510 r0 top value=40V
F1 "3101.0045" FP-3101.0045_PTH_FUSEHOLDERS-MFG 918,8182 r90 top
"High Voltage1" "DANGER HIGH VOLTAGE" IEC_HighVoltage_Medium 842,6308 r0 top
"High Voltage2" "DANGER HIGH VOLTAGE" IEC_HighVoltage_Medium 10590,6245 r0 top
J1 "691311500102" Wurth_691311500102 482,7996 r90 top
J2 "691311500102" Wurth_691311500102 480,6875 r90 top
J3 "HSEC8-160-01-L-DV-A-BL" controlCARD-120HSEC 5518.44,5644.94 r180 top locked
J4 "0312-0-15-15-34-27-10-0" Mill-Max_0312-0-15-15-34-27-10-0 7255,5966 r90 top
J5 "0312-0-15-15-34-27-10-0" Mill-Max_0312-0-15-15-34-27-10-0 7435,5966 r90 top
J6 "0312-0-15-15-34-27-10-0" Mill-Max_0312-0-15-15-34-27-10-0 7995,5966 r90 top
J7 "0312-0-15-15-34-27-10-0" Mill-Max_0312-0-15-15-34-27-10-0 8185,5966 r90 top
J8 "FTR-110-51-S-D-06" Samtec_FTR-110-51-x-D-06 6460,6151.5 r270 top
J9 "0312-0-15-15-34-27-10-0" Mill-Max_0312-0-15-15-34-27-10-0 8936,5966 r0 top
J10 "0312-0-15-15-34-27-10-0" Mill-Max_0312-0-15-15-34-27-10-0 9116,5966 r0 top
J11 "0312-0-15-15-34-27-10-0" Mill-Max_0312-0-15-15-34-27-10-0 9676,5966 r0 top
J12 "0312-0-15-15-34-27-10-0" Mill-Max_0312-0-15-15-34-27-10-0 9866,5966 r0 top
J13 "TSM-105-02-L-SV" Samtec_TSM-105-02-x-SV 4963,6134.48 r180 top
J14 "HSEC8-130-01-L-DV-A" controlCARD-180HSEC-60pinAddon 3170.29,5644.07 r180 top locked
J15 "MMCX-J-P-H-RA-TH1" FP-MMCX-J-P-H-RA-TH1_PTH_CONN_JACK-MFG 5955,6570 r180 top
J16 "FTSH-113-01-F-DV-K" FP-FTSH-113-01-F-DV-K_HDR26-MFG 5640,6148.88 r180 top
J17 "TSW-105-07-F-D" Samtec_TSW-105-07-x-D 3584,4793 r0 top
J18 "TSW-105-07-G-S" TSW-105-07-X-S 3422,4449 r180 top
J19 "TSW-102-23-T-S" Samtec_TSW-102-23-X-S 2839.58,5282 r270 top
J20 "215307-3" TE_215307-3 8656,5835 r0 top
J21 "215307-3" TE_215307-3 6975,5835 r0 top
L1 "VI-19158A" FP-VI-19158A_PTH_INDUCTOR_47MM_39MM-MFG 5451.7,3047.46 r0 top
L2 "SER2915H-472KL" SER2915H 9139,7958 r90 top value=4.7uH
L3 "74279262" 0603 5554.52,1598.44 r90 top value="120 ohm"
L4 "74279262" 0603 6763,4510 r270 top value="120 ohm"
L5 "74279262" 0603 6924.52,1608.44 r90 top value="120 ohm"
L6 "74279262" 0603 5364,4524 r270 top value="120 ohm"
L7 "7448052303" WE-CMBNC_XL 1329,7284 r0 top value=2.5mH
LBL1 "THT-14-423-10" Label_650x200 1211,276 r0 top
NT1 "Net-Tie" Net-Tie_50milWide_30milLong 2639.6,5053 r0 top net-tie
Q1 "C3M0065100K" FP-C3M0065100K_TO247-4-MFG 7447,5711 r0 bottom
Q2 "C3M0065100K" FP-C3M0065100K_TO247-4-MFG 9101.89,5711 r0 bottom
Q16 "C3M0065100K" FP-C3M0065100K_TO247-4-MFG 8199.44,5711 r0 bottom
Q17 "C3M0065100K" FP-C3M0065100K_TO247-4-MFG 9854.33,5711 r0 bottom
R1 "RC0603FR-0713KL" 0603L 4748,1667 r0 top value=13.0k
R2 "CRCW060310R0FKEA" 0603L 4218,2480 r90 bottom value=10.0
R3 "CRCW060310R0FKEA" 0603L 4229,2907.56 r90 bottom value=10.0
R4 "CRCW060310R0FKEA" 0603L 4226,3333 r90 bottom value=10.0
R5 "CRCW060310R0FKEA" 0603L 4222,3751 r90 bottom value=10.0
R6 "VSML3923S9-0M50F" FP-VSML3923S9-0M50F_SMT_10MM0_5MM75-MFG 4174.39,3637.21 r0 top
R7 "VSML3923S9-0M50F" FP-VSML3923S9-0M50F_SMT_10MM0_5MM75-MFG 4174.39,3213.88 r0 top
R8 "VSML3923S9-0M50F" FP-VSML3923S9-0M50F_SMT_10MM0_5MM75-MFG 4174.39,2790.55 r0 top
R9 "VSML3923S9-0M50F" FP-VSML3923S9-0M50F_SMT_10MM0_5MM75-MFG 4174.39,2367.21 r0 top
R10 "CRCW06030000Z0EA" 0603L 3753,4163 r0 top value=0
R11 "VSME1518SV-M125F" FP-VSME1518SV-M125F_SMT_RES_15MM0_18MM0-MFG 4178.4,2999 r0 top
R12 "RCS06030000Z0EA" 0603 5398.5,5446 r180 top value=0
R13 "CRCW06030000Z0EA" 0603L 3752.56,4108 r0 top value=0
R14 "CRCW0603100KFKEA" 0603L 7133.56,6719 r0 top value=100k
R15 "CRCW060310R0FKEA" 0603L 4125,3750.44 r90 bottom value=10.0
R16 "ERJ-3EKF1000V" 0603 6554,6357 r0 top value=100
R17 "CRCW060310R0FKEA" 0603L 4130,3334 r90 bottom value=10.0
R18 "CRCW060310R0FKEA" 0603L 4129,2907.56 r90 bottom value=10.0
R19 "RC0603FR-074K7L" 0603 6171,6196 r90 top value=4.70k
R20 "CRCW060310R0FKEA" 0603L 4126,2481 r90 bottom value=10.0
R21 "CRCW06035R11FKEA" 0603L 7245,6189.56 r90 top value=5.11
R22 "CRCW06035R11FKEA" 0603L 8906,6184.44 r90 top value=5.11
R23 "RC0603FR-071RL" 0603L 7332,6161 r180 top value=1.00
R24 "RC0603FR-071RL" 0603L 8989.44,6160 r180 top value=1.00
R25 "CRCW060310K0FKEA" 0603L 7333,6215 r180 top value=10.0k
R26 "CRCW060310K0FKEA" 0603L 8990,6215 r180 top value=10.0k
R27 "CRCW201030R0JNEF" 2010L 6922.81,4279.62 r0 top value=30
R28 "CRCW201030R0JNEF" 2010L 6919.43,4409.62 r0 top value=30
R29 "CRCW201030R0JNEF" 2010L 6919.43,4539.62 r0 top value=30
R30 "CRCW201030R0JNEF" 2010L 6187.05,4566.97 r0 top value=30
R31 "CRCW201030R0JNEF" 2010L 6187.05,4436 r0 top value=30
R32 "CRCW201030R0JNEF" 2010L 6185.61,4304.73 r0 top value=30
R33 "CRCW201030R0JNEF" 2010L 5948.39,4567 r0 top value=30
R34 "CRCW201030R0JNEF" 2010L 5949.26,4437 r0 top value=30
R35 "CRCW201030R0JNEF" 2010L 5949.26,4304.73 r0 top value=30
R36 "CRCW201030R0JNEF" 2010L 5204.52,4197.45 r180 top value=30
R37 "CRCW201030R0JNEF" 2010L 5204.52,4327.45 r180 top value=30
R38 "CRCW201030R0JNEF" 2010L 5204.52,4457.45 r180 top value=30
R39 "RC0603FR-074K7L" 0603 6419.5,6357 r180 top value=4.70k
R40 "RC0603FR-0749R9L" 0603 4464,4873 r180 top value=49.9
R41 "RC0603FR-071KL" 0603 6417,6602.5 r270 top value=1.00k
R42 "RC0603FR-0710KL" 0603 4593,4808 r180 top value=10.0k
R43 "CRCW0603100KFKEA" 0603L 9710,5000 r90 top value=100k
R44 "CRCW201030R0JNEF" 2010L 5404.91,1547.61 r180 top value=30
R45 "CRCW201030R0JNEF" 2010L 5404.91,1677.61 r180 top value=30
R46 "CRCW201030R0JNEF" 2010L 5404.91,1807.96 r180 top value=30
R47 "CRCW201030R0JNEF" 2010L 6121.73,1788.61 r180 top value=30
R48 "CRCW201030R0JNEF" 2010L 6121.73,1658.61 r180 top value=30
R49 "CRCW201030R0JNEF" 2010L 6121.73,1528.61 r180 top value=30
R50 "CRCW201030R0JNEF" 2010L 6359.91,1788.96 r180 top value=30
R51 "CRCW201030R0JNEF" 2010L 6359.91,1658.61 r180 top value=30
R52 "CRCW201030R0JNEF" 2010L 6359.91,1528.61 r180 top value=30
R53 "CRCW201030R0JNEF" 2010L 7112.63,1634.07 r0 top value=30
R54 "CRCW201030R0JNEF" 2010L 7112.63,1771.14 r0 top value=30
R55 "CRCW201030R0JNEF" 2010L 7112.63,1901 r0 top value=30
R56 "RC0603FR-071KL" 0603 6658,6660.5 r180 top value=1.00k
R57 "RC0603FR-0710KL" 0603 4592.5,4873 r180 top value=10.0k
R58 "RC0603FR-0710RL" 0603 6256,6569.5 r180 top value=10.0
R59 "RC0603FR-0749R9L" 0603 6127,6569 r180 top value=49.9
R60 "RC1206FR-0720RL" 1206L 9205,4967 r90 top value=20.0
R61 "RC1206FR-0720RL" 1206L 9305,4966.85 r90 top value=20.0
R62 "CRCW12065R36FKEA" 1206 6780,6616.5 r90 top value=5.36
R63 "RC0603FR-072K15L" 0603 4722.5,4873 r180 top value=2.15k
R64 "CRCW06035R11FKEA" 0603L 8011,6187 r90 top value=5.11
R65 "CRCW06035R11FKEA" 0603L 9660,6189 r90 top value=5.11
R66 "ERJ-3EKF2202V" 0603 6491.5,6505.5 r180 top value=22.0k
R67 "RC0603FR-071KL" 0603 6659.89,6582.5 r180 top value=1.00k
R68 "RCS06030000Z0EA" 0603 6975,6443.5 r270 top value=0
R69 "RC0603FR-071RL" 0603L 8094,6161.44 r180 top value=1.00
R70 "RC0603FR-071RL" 0603L 9742.56,6161 r180 top value=1.00
R71 "CRCW060310K0FKEA" 0603L 8094,6216 r180 top value=10.0k
R72 "CRCW060310K0FKEA" 0603L 9742.56,6216 r180 top value=10.0k
R73 "RC0603FR-071K05L" 0603 6619.5,6505.5 r180 top value=1.05k
R74 "RCS06030000Z0EA" 0603 6907,6443.5 r270 top value=0
R75 "CR0603-FX-4991ELF" 0603 3315.5,6376 r180 top value=4.99k
R76 "ERJ-8ENF8453V" 1206 3566.09,6734 r180 top value=845k
R77 "ERJ-8ENF8453V" 1206 3368.09,6734 r180 top value=845k
R78 "ERJ-8ENF8453V" 1206 3170.09,6734 r180 top value=845k
R79 "RCS06030000Z0EA" 0603 3085,6635 r180 top value=0
R80 "ERJ-8ENF9091V" 1206 2972,6733 r0 top value=9.09k
R81 "RC0603FR-0715KL" 0603 6010,5252.5 r90 top value=15.0k
R82 "RC0603FR-074K64L" 0603 5566.5,5190 r0 top value=4.64k
R83 "RCS06030000Z0EA" 0603 6135,5315 r90 top value=0
R84 "RC0603FR-074K64L" 0603 5759.5,5190 r0 top value=4.64k
R85 "RC0603FR-074K64L" 0603 5566.5,5253 r0 top value=4.64k
R86 "RC0603FR-072K15L" 0603 4722.5,4808 r180 top value=2.15k
R87 "RCS06030000Z0EA" 0603 5398.5,5383 r0 top value=0
R88 "RC0603FR-0710KL" 0603 4036,5334 r270 top value=10.0k
R89 "RC0603FR-076K49L" 0603 3341,4168 r180 top value=6.49k
R90 "ERJ-3EKF1002V" 0603 3341,4106 r0 top value=10.0k
R91 "RCS06030000Z0EA" 0603 6170,5441 r180 top value=0
R92 "RCS06030000Z0EA" 0603 6207,5345 r270 top value=0
R93 "RC0603FR-074K64L" 0603 5760,5253 r0 top value=4.64k
R94 "RC0603FR-0715KL" 0603 5896,5345 r180 top value=15.0k
R95 "RC0603FR-0710KL" 0603 4361,5987 r180 top value=10.0k
R96 "RC0603FR-0710KL" 0603 4097.47,4732 r0 top value=10.0k
R140 "RC0603FR-0710KL" 0603 4032,5045 r90 top value=10.0k
R152 "CRCW06032R21FKEA" 0603L 5743.92,1804.28 r90 top value=2.21
R153 "CRCW06032R21FKEA" 0603L 6567.19,4289.42 r270 top value=2.21
R155 "CRCW06032R21FKEA" 0603L 5863.92,1807.08 r90 top value=2.21
R156 "CRCW06032R21FKEA" 0603L 6441.7,4290.6 r270 top value=2.21
R157 "CRCW060310K0FKEA" 0603L 5923.92,1807.08 r90 top value=10.0k
R158 "CRCW060310K0FKEA" 0603L 5687.47,1804.28 r90 top value=10.0k
R159 "CRCW060310K0FKEA" 0603L 6386.88,4290.6 r270 top value=10.0k
R160 "CRCW060310K0FKEA" 0603L 6627.19,4287.8 r270 top value=10.0k
R168 "CRCW06032R21FKEA" 0603L 6611.76,1814 r90 top value=2.21
R169 "CRCW06032R21FKEA" 0603L 5664,4301.56 r270 top value=2.21
R170 "CRCW06032R21FKEA" 0603L 6738.74,1807.11 r90 top value=2.21
R171 "CRCW06032R21FKEA" 0603L 5545.22,4299.89 r270 top value=2.21
R172 "CRCW060310K0FKEA" 0603L 6795.5,1807.11 r90 top value=10.0k
R173 "CRCW060310K0FKEA" 0603L 6554.99,1814 r90 top value=10.0k
R174 "CRCW060310K0FKEA" 0603L 5485.22,4299.89 r270 top value=10.0k
R175 "CRCW060310K0FKEA" 0603L 5717.54,4303.44 r270 top value=10.0k
SR1 "IPP120N08S403AKSA1_hr" FP-IPP120N08S403AKSA1_hr_TO220-MFG 6834.28,4665.83 r180 bottom
SR2 "IPP120N08S403AKSA1_hr" FP-IPP120N08S403AKSA1_hr_TO220-MFG 6384.38,4665.83 r180 bottom
SR3 "IPP120N08S403AKSA1_hr" FP-IPP120N08S403AKSA1_hr_TO220-MFG 5934.48,4665.83 r180 bottom
SR4 "IPP120N08S403AKSA1_hr" FP-IPP120N08S403AKSA1_hr_TO220-MFG 5484.58,4665.83 r180 bottom
SR5 "IPP120N08S403AKSA1_hr" FP-IPP120N08S403AKSA1_hr_TO220-MFG 5484.58,1426.95 r0 bottom
SR6 "IPP120N08S403AKSA1_hr" FP-IPP120N08S403AKSA1_hr_TO220-MFG 5934.48,1426.95 r0 bottom
SR7 "IPP120N08S403AKSA1_hr" FP-IPP120N08S403AKSA1_hr_TO220-MFG 6384.38,1426.95 r0 bottom
SR8 "IPP120N08S403AKSA1_hr" FP-IPP120N08S403AKSA1_hr_TO220-MFG 6834.28,1426.95 r0 bottom
T1 "CST2010-100LB" CST2010 7116,7176 r90 top value=8.5mH
T2 "CB125-14-QY" Panduit_CB125-14-QY 1961.56,4423.45 r0 top
T3 "CB125-14-QY" Panduit_CB125-14-QY 1961.56,5086.97 r0 top
T4 "CB125-14-QY" Panduit_CB125-14-QY 1961.56,5750.49 r0 top
T5 "CB125-14-QY" Panduit_CB125-14-QY 3309.56,2918.97 r0 top
T7 "CB125-14-QY" Panduit_CB125-14-QY 3309.56,2255.45 r0 top
T8 "CST2010-100LB" CST2010 10191.09,5004 r0 top value=8.5mH
T9 "CB125-14-QY" Panduit_CB125-14-QY 3309.56,3582.49 r0 top
T10 "760390014" Wurth_760390013 3909,6415 r180 top value=475uH
TP1 "5005" Keystone5005 2727,4928 r0 top
TP2 "5122" Keystone5122 4327,4982 r0 top
TP3 "5122" Keystone5122 4556,4982 r0 top
TP4 "5005" Keystone5005 2832,4226 r0 top
U1 "OPA836IDBVR" DBV0006A_L 6517,6619.5 r90 top
U2 "TPS79633DCQ" DCQ0006A_N 3732,5200 r180 top
U3 "TPS7B6950DBVR" DBV0005A_N 3397,6494 r180 top
U4 "SN6501QDBVRQ1" DBV0005A_L 4203,6415 r0 top
U5 "AMC1311BDWVR" DWV0008A 3029,6311 r270 top
U6 "OPA365AIDBVT" DBV0005A_N 5904,5224 r270 top
U7 "LM35DT/NOPB" FP-LM35DT-NOPB-Recommended_Land_Pattern_hr 7595.66,4757 r270 bottom
U8 "LM35DT/NOPB" NEB0003F 8829,4648 r180 top
U9 "INA240A2PWR" PW0008A_L 3554,4133 r180 top
U10 "PINA293A3QDBVRQ1" DBV0005A_N 3555,4275 r0 top
U14 "UCC27524AQDRQ1" D0008A_N 5767.47,1607.07 r90 top
U15 "UCC27524AQDRQ1" D0008A_N 6554.39,4493.52 r270 top
U17 "UCC27524AQDRQ1" D0008A_N 6664.91,1614.24 r90 top
U18 "UCC27524AQDRQ1" D0008A_N 5632.42,4497.17 r270 top
ZZ1 "This Assembly Note is for PCB labels only" AssemblyNoteLabel 19946,3734 r0 top
ZZ2 "These assemblies are ESD sensitive, ESD precautions shall be observed." AssemblyNote 11762,1787 r90 top
ZZ3 "These assemblies must be clean and free from flux and all contaminants. Use of no clean flux is not acceptable." AssemblyNote 11640,296 r90 top
ZZ4 "These assemblies must comply with workmanship standards IPC-A-610 Class 2, unless otherwise specified." AssemblyNote 11402,622 r90 top

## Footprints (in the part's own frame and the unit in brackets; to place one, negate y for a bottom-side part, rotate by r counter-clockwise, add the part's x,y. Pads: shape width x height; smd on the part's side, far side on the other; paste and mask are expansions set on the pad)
0603 [mm] "0603 from SM-752 data"
  rect 1x0.95 smd: 1(-0.8,0) 2(0.8,0)
  silkscreen extent -1.52,-0.69 1.52,0.69, body extent -0.87,-0.47 0.87,0.47, height 1
0603L [mm] "0603 from SM-752 data"
  rect 0.8x0.85 smd: 1(-0.7,0) 2(0.7,0)
  silkscreen extent -0.07,-0.33 0.07,0.33, body extent -0.87,-0.47 0.87,0.47, height 1
0805_150 [mm] "0805 / 1.5 mm height"
  rect 1.15x1.45 smd: 1(-0.9,0) 2(0.9,0)
  silkscreen extent -0.1,-0.8 0.1,0.8, body extent -1.1,-0.72 1.1,0.72, height 1.5
0805_HV [mil] "0805 with 30mil clearance between pads"
  rect 50x63 smd: 1(-40,0) 2(40,0)
  silkscreen extent -74,-40 74,40, body extent -43,-29 43,29, height 57
1206 [mm] "1206 from SM-752 data"
  rect 1.3x1.85 smd: 1(-1.45,0) 2(1.45,0)
  silkscreen extent -2.4,-1.21 2.4,1.21, body extent -1.7,-0.9 1.7,0.9, height 1.35
1206_150 [mm] "1206"
  rect 1.1x1.6 smd: 1(-1.7,0) 2(1.7,0)
  silkscreen extent -0.9,-1 0.9,1, body extent -1.75,-0.95 1.75,0.95, height 1.5
1206L [mm] "1206 from SM-752 data"
  rect 1.1x1.75 smd: 1(-1.35,0) 2(1.35,0)
  silkscreen extent -0.4,-0.77 0.4,0.77, body extent -1.7,-0.9 1.7,0.9, height 1.35
1210_270 [mm] "1210"
  rect 1.3x2.7 smd: 1(-1.45,0) 2(1.45,0)
  silkscreen extent -2.32,-1.57 2.32,1.57, body extent -1.7,-1.35 1.7,1.35, height 2.7
2010L [mm]
  rect 1.2x2.7 smd: 1(-2.2,0) 2(2.2,0)
  silkscreen extent -1.2,-1.25 1.2,1.25, body extent -2.73,-1.45 2.73,1.45, height 1.66
2220_450 [mm] "Laird recommended land pattern"
  rrect3% 3.07x6.1 smd: 1(-3.06,0) 2(3.06,0)
  silkscreen extent -1.3,-3 1.3,3, body extent -2.8,-2.54 2.79,2.54, height 4.5
AssemblyNote [mil] "Assembly Note"
AssemblyNoteLabel [mil] "Assembly Note for PCB Labels"
B32926_42.5mm [mm] "Epcos film capacitors, 37.5mm spacing"
  rect 1.7x1.7 hole 1.2: 1(-18.75,0)
  round 1.7 hole 1.2: 2(18.75,0)
  silkscreen extent -20.75,-14 20.75,14, body extent -20.75,-14 20.75,14, height 42.5
B41896_1250x2000 [mm] "TH, 2-Leads, Dia 12.5mm, Pin Spacing 5mm"
  rect 1.4x1.4 hole 0.9: 1(-2.5,0)
  round 1.4 hole 0.9: 2(2.5,0)
  silkscreen extent -6.5,-6.5 6.5,6.5, body extent -6.5,-6.5 6.51,6.5, height 22.01
controlCARD-120HSEC [mm] "Pads are not numbered according to Samtec datasheet."
  rect 0.5x2.724 smd: 1(-23.357,-1.678) 2(-23.357,1.722) 3(-22.557,-1.678) 4(-22.557,1.722) 5(-21.757,-1.678) 6(-21.757,1.722) 7(-20.957,-1.678) 8(-20.957,1.722) 9(-20.157,-1.678) 10(-20.157,1.722) 11(-19.357,-1.678) 12(-19.357,1.722) 13(-18.557,-1.678) 14(-18.557,1.722) 15(-17.757,-1.678) 16(-17.757,1.722) 17(-16.957,-1.678) 18(-16.957,1.722) 19(-16.157,-1.678) 20(-16.157,1.722) 21(-15.357,-1.678) 22(-15.357,1.722) 23(-14.557,-1.678) 24(-14.557,1.722) 25(-13.757,-1.678) 26(-13.757,1.722) 27(-12.957,-1.678) 28(-12.957,1.722) 29(-12.157,-1.678) 30(-12.157,1.722) 31(-11.357,-1.678) 32(-11.357,1.722) 33(-10.557,-1.678) 34(-10.557,1.722) 35(-9.757,-1.678) 36(-9.757,1.722) 37(-8.957,-1.678) 38(-8.957,1.722) 39(-8.157,-1.678) 40(-8.157,1.722) 41(-7.357,-1.678) 42(-7.357,1.722) 43(-6.557,-1.678) 44(-6.557,1.722) 45(-5.757,-1.678) 46(-5.757,1.722) 47(-4.957,-1.678) 48(-4.957,1.722) 49(-4.157,-1.678) 50(-4.157,1.722) 51(-3.357,-1.678) 52(-3.357,1.722) 53(-2.557,-1.678) 54(-2.557,1.722) 55(-1.757,-1.678) 56(-1.757,1.722) 57(2.243,-1.678) 58(2.243,1.722) 59(3.043,-1.678) 60(3.043,1.722) 61(3.843,-1.678) 62(3.843,1.722) 63(4.643,-1.678) 64(4.643,1.722) 65(5.443,-1.678) 66(5.443,1.722) 67(6.243,-1.678) 68(6.243,1.722) 69(7.043,-1.678) 70(7.043,1.722) 71(7.843,-1.678) 72(7.843,1.722) 73(8.643,-1.678) 74(8.643,1.722) 75(9.443,-1.678) 76(9.443,1.722) 77(10.243,-1.678) 78(10.243,1.722) 79(11.043,-1.678) 80(11.043,1.722) 81(11.843,-1.678) 82(11.843,1.722) 83(12.643,-1.678) 84(12.643,1.722) 85(13.443,-1.678) 86(13.443,1.722) 87(14.243,-1.678) 88(14.243,1.722) 89(15.043,-1.678) 90(15.043,1.722) 91(15.843,-1.678) 92(15.843,1.722) 93(16.643,-1.678) 94(16.643,1.722) 95(17.443,-1.678) 96(17.443,1.722) 97(18.243,-1.678) 98(18.243,1.722) 99(19.043,-1.678) 100(19.043,1.722) 101(19.843,-1.678) 102(19.843,1.722) 103(20.643,-1.678) 104(20.643,1.722) 105(21.443,-1.678) 106(21.443,1.722) 107(22.243,-1.678) 108(22.243,1.722) 109(23.043,-1.678) 110(23.043,1.722) 111(23.843,-1.678) 112(23.843,1.722) 113(24.643,-1.678) 114(24.643,1.722) 115(25.443,-1.678) 116(25.443,1.722) 117(26.243,-1.678) 118(26.243,1.722) 119(27.043,-1.678) 120(27.043,1.722)
  round 0.025 hole 1.27 unplated mask+0.876: 181(-24.857,0.022) 182(28.543,1.522)
  round 1.348 hole 0.84: 185(-27.207,0.022) 186(30.893,0.022)
  silkscreen extent -32.11,-3.86 35.8,3.9, body extent -31.75,-3.48 35.3,3.52, height 12.35
controlCARD-180HSEC-60pinAddon [mm] "Pads are not numbered according to datasheet."
  round 0.025 hole 1.27 unplated mask+0.876: 61(-13.1,0) 62(13.1,1.5)
  rect 0.5x2.724 smd: 121(-11.6,-1.7) 122(-11.6,1.7) 123(-10.8,-1.7) 124(-10.8,1.7) 125(-10,-1.7) 126(-10,1.7) 127(-9.2,-1.7) 128(-9.2,1.7) 129(-8.4,-1.7) 130(-8.4,1.7) 131(-7.6,-1.7) 132(-7.6,1.7) 133(-6.8,-1.7) 134(-6.8,1.7) 135(-6,-1.7) 136(-6,1.7) 137(-5.2,-1.7) 138(-5.2,1.7) 139(-4.4,-1.7) 140(-4.4,1.7) 141(-3.6,-1.7) 142(-3.6,1.7) 143(-2.8,-1.7) 144(-2.8,1.7) 145(-2,-1.7) 146(-2,1.7) 147(-1.2,-1.7) 148(-1.2,1.7) 149(-0.4,-1.7) 150(-0.4,1.7) 151(0.4,-1.7) 152(0.4,1.7) 153(1.2,-1.7) 154(1.2,1.7) 155(2,-1.7) 156(2,1.7) 157(2.8,-1.7) 158(2.8,1.7) 159(3.6,-1.7) 160(3.6,1.7) 161(4.4,-1.7) 162(4.4,1.7) 163(5.2,-1.7) 164(5.2,1.7) 165(6,-1.7) 166(6,1.7) 167(6.8,-1.7) 168(6.8,1.7) 169(7.6,-1.7) 170(7.6,1.7) 171(8.4,-1.7) 172(8.4,1.7) 173(9.2,-1.7) 174(9.2,1.7) 175(10,-1.7) 176(10,1.7) 177(10.8,-1.7) 178(10.8,1.7) 179(11.6,-1.7) 180(11.6,1.7)
  silkscreen extent -14.68,-3.88 14.68,3.88, body extent -14.3,-3.5 14.3,3.5, height 7.95
CST2010 [mm] "Coilcraft Current Sense Transformer"
  rrect8% 2.34x1.19 smd: 1(-9.04,5.08) 2(-9.04,2.54) 3(-9.04,0) 4(-9.04,-2.54) 5(-9.04,-5.08) 6(9.04,-5.08) 7(9.04,-2.54) 8(9.04,0) 9(9.04,2.54) 10(9.04,5.08)
  rrect2% 7.24x4.27 smd: 11(-0.1,5.62) 12(0,-5.62)
  body extent -9.6,-7.28 9.6,7.27, height 10.82
D0008A_N [mm] "SOIC, 8-Leads, Body 4.9x3.9mm, Pitch 1.27mm, IPC Medium Density"
  oval 1.45x0.6 smd: 1(-2.725,1.905) 2(-2.725,0.635) 3(-2.725,-0.635) 4(-2.725,-1.905) 5(2.725,-1.905) 6(2.725,-0.635) 7(2.725,0.635) 8(2.725,1.905)
  silkscreen extent -3.3,-2.5 0.9,2.5, body extent -3,-2.45 3,2.45, height 1.63
DBV0005A_L [mm] "SOT23, 5-Leads, Body 2.9x1.6mm, Pitch 0.95mm, Lead Span 2.8mm, IPC High Density"
  rrect18% 0.8x0.55 smd: 1(-1.275,0.95) 2(-1.275,0) 3(-1.275,-0.95) 4(1.275,-0.95) 5(1.275,0.95)
  silkscreen extent -0.35,-1.55 0.35,1.55, body extent -1.42,-1.46 1.42,1.46, height 1.09
DBV0005A_N [mm] "SOT23, 5-Leads, Body 2.9x1.6mm, Pitch 0.95mm, Lead Span 2.8mm, IPC Medium Density"
  rrect17% 1x0.6 smd: 1(-1.375,0.95) 2(-1.375,0) 3(-1.375,-0.95) 4(1.375,-0.95) 5(1.375,0.95)
  silkscreen extent -1.63,-1.55 0.38,1.55, body extent -1.42,-1.46 1.42,1.46, height 1.09
DBV0006A_L [mm] "SOT23, 6-Leads, Body 2.9x1.6mm, Pitch 0.95mm, Lead Span 2.8mm, IPC High Density"
  rrect18% 0.8x0.55 smd: 1(-1.275,0.95) 2(-1.275,0) 3(-1.275,-0.95) 4(1.275,-0.95) 5(1.275,0) 6(1.275,0.95)
  silkscreen extent -1.55,-1.53 0.55,1.53, body extent -1.42,-1.46 1.42,1.46, height 1.12
DCQ0006A_N [mm] "SOT223, 6-Leads, Body 6.6x7.3mm (max), Pitch 1.27mm, IPC Medium Density"
  rrect17% 2.1x0.6 smd: 1(-2.975,2.54) 2(-2.975,1.27) 3(-2.975,0) 4(-2.975,-1.27) 5(-2.975,-2.54)
  rrect5% 2.1x3.2 smd: 6(2.975,0)
  silkscreen extent -1.5,-3.27 1.5,3.27, body extent -3.54,-3.25 3.54,3.25, height 1.8
DWV0008A [mm] "SOIC, 8-Leads, Body 5.95x7.6mm (max), Pitch 1.27mm"
  rrect17% 1.8x0.6 smd: 1(-5.45,1.905) 2(-5.45,0.635) 3(-5.45,-0.635) 4(-5.45,-1.905) 5(5.45,-1.905) 6(5.45,-0.635) 7(5.45,0.635) 8(5.45,1.905)
  silkscreen extent -6.25,-2.95 2.98,2.95, body extent -5.77,-2.92 5.77,2.93, height 2.67
E_900x700x900 [mm] "TH, 2- Leads, Body 9x7mm, Pin Spacing 7.5mm"
  round 1.4 hole 0.9: 1(-3.75,0) 2(3.75,0)
  silkscreen extent -4.5,-3.5 4.5,3.5, body extent -4.49,-3.5 4.49,3.5, height 11.96
FP-3101.0045_PTH_FUSEHOLDERS-MFG [mm]
  rrect5% 2x2 hole 1.3 paste-1000 mask+0: 1(-2.54,3.81)
  round 2 hole 1.3 paste-1000 mask+0: 2(2.54,3.81) 3(-2.54,-3.81) 4(2.54,-3.81)
  silkscreen extent -6.97,-6.25 6.25,6.25, body extent -6.35,-6.35 6.35,6.35, height 0.25
FP-C3M0065100K_TO247-4-MFG [mm]
  rrect100% 2.29x4.06 hole 1.78 paste-1000 mask+0: 1(5.08,-16.202) 2(0,-16.202) 3(-2.54,-16.202) 4(-5.08,-16.202)
  round 6 hole 6 unplated paste-1000 mask+0: ""(0,5.555)
  silkscreen extent -8.06,-16.33 8.07,11.8, body extent -7.97,-16.43 7.97,11.8, height 5.21
FP-C6D10065A_TO-220-2-Recommended_Land_Pattern_Horizontal [mm]
  rrect100% 1.87x3.048 hole 1.27 paste-1000 mask+0: 1(2.54,-11.455) 2(-2.54,-11.455)
  round 6 hole 6 unplated paste-1000 mask+0: ""(0,4.858)
  silkscreen extent -5.21,-13.67 5.21,7.81, body extent -5.02,-11.7 5.02,7.66, height 4.7
FP-FTSH-113-01-F-DV-K_HDR26-MFG [mm] "Header, 2.54mm, 13x2, TH"
  rrect14% 0.74x2.79 smd paste+0 mask+0: 1(-7.62,-2.035) 2(-7.62,2.035) 3(-6.35,-2.035) 4(-6.35,2.035) 5(-5.08,-2.035) 6(-5.08,2.035) 7(-3.81,-2.035) 8(-3.81,2.035) 9(-2.54,-2.035) 10(-2.54,2.035) 11(-1.27,-2.035) 12(-1.27,2.035) 13(0,-2.035) 14(0,2.035) 15(1.27,-2.035) 16(1.27,2.035) 17(2.54,-2.035) 18(2.54,2.035) 19(3.81,-2.035) 20(3.81,2.035) 21(5.08,-2.035) 22(5.08,2.035) 23(6.35,-2.035) 24(6.35,2.035) 25(7.62,-2.035) 26(7.62,2.035)
  silkscreen extent -8.32,-4.14 8.32,0.27, body extent -8.42,-3.53 8.42,3.53, height 0.25
FP-IPP120N08S403AKSA1_hr_TO220-MFG [mm]
  rrect5% 1.85x1.85 hole 1.2 paste-1000 mask+0: 1(2.54,-12.625)
  round 1.85 hole 1.2 paste-1000 mask+0: 2(0,-12.625) 3(-2.54,-12.625)
  round 6 hole 6 unplated paste-1000 mask+0: ""(0,5.025)
  silkscreen extent -5.1,-14.27 5.1,7.98, body extent -5,-12.88 5,7.82, height 4.4
FP-LM35DT-NOPB-Recommended_Land_Pattern_hr [mm]
  rrect6% 1.7x1.7 hole 1.2 paste-1000 mask+0: 1(2.54,-11.362)
  round 1.7 hole 1.2 paste-1000 mask+0: 2(0,-11.362) 3(-2.54,-11.362)
  round 6 hole 6 unplated paste-1000 mask+0: ""(0,4.697)
  silkscreen extent -5.52,-12.91 5.52,7.75, body extent -5.27,-11.62 5.27,7.43, height 4.7
FP-MMCX-J-P-H-RA-TH1_PTH_CONN_JACK-MFG [mm]
  rrect7% 1.34x1.34 hole 0.84 paste-1000 mask+0: 1(0,0)
  round 1.34 hole 0.84 paste-1000 mask+0: 2(-1.27,1.27) 3(1.27,1.27) 4(-1.27,-1.27) 5(1.27,-1.27)
  silkscreen extent -2.54,-0.23 1.82,1.82, body extent -2.04,-4.91 2.04,2.04, height 0.25
FP-TPSMB51CA_DO214AA-MFG [mm]
  rrect5% 2.16x2.26 smd paste+0 mask+0: 1(-2.45,0) 2(2.45,0)
  silkscreen extent -2.28,-1.97 2.28,1.97, body extent -3.63,-2.07 3.63,2.07, height 0.25
FP-VI-19158A_PTH_INDUCTOR_47MM_39MM-MFG [mm]
  rrect3% 12.1x3.1 hole 2.5 slot 11.5 at 0 deg paste-1000 mask+0: 1(10,9.65)
  rrect100% 12.1x3.1 hole 2.5 slot 11.5 at 0 deg paste-1000 mask+0: 2(-10,3.9) 3(10,-5.9) 4(-10,-11.65)
  silkscreen extent -23.5,-19.5 24.23,19.5, body extent -23.6,-19.6 23.6,19.6, height 0.25
FP-VSME1518SV-M125F_SMT_RES_15MM0_18MM0-MFG [mm]
  rrect2% 5.2x19 smd paste+0 mask+0: 1(-5.4,0) 2(5.4,0)
  silkscreen extent -2.42,-9.13 2.42,9.13, body extent -7.5,-9 7.5,9, height 2.75
FP-VSML3923S9-0M50F_SMT_10MM0_5MM75-MFG [mm]
  rrect4% 2.7x6.2 smd paste+0 mask+0: 1(-4.15,0) 2(4.15,0)
  silkscreen extent -2.42,-3 2.42,3, body extent -5,-2.87 5,2.87, height 1.85
IEC_HighVoltage_Medium [mil]
  silkscreen extent -217,-176 217,200
Keystone5005 [mil] "Keystone Compact loops"
  round 87 hole 63: 1(0,0)
  silkscreen extent -70,-70 70,70, body extent -63,-63 62,63, height 225
Keystone5122 [mil] "Keystone Compact loops"
  round 87 hole 63: 1(0,0)
  silkscreen extent -70,-70 70,70, body extent -63,-63 62,63, height 225
Label_650x200 [mil] "Thermal Transfer Label"
  round 1 on Mech13: 0(0,0)
  silkscreen extent -325,-100 325,100, body extent -325,-100 325,100, height 1
LTST-C193_Green [mm] "SMD, 2-Leads, Body1.6x0.8mm"
  rect 0.8x0.8 smd: 1(-0.75,0) 2(0.75,0)
  body extent -0.85,-0.45 0.85,0.45, height 0.45
Mill-Max_0312-0-15-15-34-27-10-0 [mm] "Pin Receptacle, .032-.046\" .075\" Dia, Gold, TH"
  round 2.45 hole 1.905: 1(0,0)
  silkscreen extent -1.52,-1.52 1.52,1.52, body extent -1.15,-1.15 1.16,1.15, height 0.46
NEB0003F [mm] "TO-220-3"
  rrect25% 1.8x1.8 hole 1.2: 1(-2.54,0)
  round 1.8 hole 1.2: 2(0,0) 3(2.54,0)
  body extent -5.29,-1.71 5.29,2.86, height 18.88
Net-Tie_50milWide_30milLong [mil] "50mil net tie, no solder mask opening, no solder paste"
  rect 30x50 smd paste-20 mask-20: 1(-15,0) 2(15,0)
Nichicon_3500x3500_Snap [mm]
  rrect3% 3x3 hole 2.2: 1(-5,0)
  round 3 hole 2.2: 2(5,0)
  silkscreen extent -18.1,-18.1 18.1,18.1, body extent -18,-18 18.01,18, height 37.01
Panduit_CB125-14-QY [mil] "Terminal 125A Lug"
  rrect1% 945x620 hole 260 copper offset -52.5,0 paste-250: 1(0,0)
  silkscreen extent -1560,-310 420,310, body extent -1560,-310 420,310, height 1385
PW0008A_L [mm] "TSOP, 8-Leads, Body 3x4.4mm, Pitch 0.65mm, IPC High Density"
  oval 1.2x0.4 smd: 1(-2.85,0.975) 2(-2.85,0.325) 3(-2.85,-0.325) 4(-2.85,-0.975) 5(2.85,-0.975) 6(2.85,-0.325) 7(2.85,0.325) 8(2.85,0.975)
  silkscreen extent -3.2,-1.55 1.85,1.55, body extent -3.21,-1.5 3.21,1.5, height 1.2
R73_1800x500x1100 [mm] "TH, 2-Leads, Body 18x5mm, Pin Spacing 15mm"
  round 1.6 hole 1.1: 1(-7.5,0) 2(7.5,0)
  silkscreen extent -9.15,-2.6 9.15,2.6, body extent -9.15,-2.6 9.15,2.6, height 11.1
Samtec_FTR-110-51-x-D-06 [mm] "Header, 1.27mm, 10x2, SMT"
  rect 2.87x0.711 smd: 1(-2.705,5.715) 2(2.705,5.715) 3(-2.705,4.445) 4(2.705,4.445) 5(-2.705,3.175) 6(2.705,3.175) 7(-2.705,1.905) 8(2.705,1.905) 9(-2.705,0.635) 10(2.705,0.635) 11(-2.705,-0.635) 12(2.705,-0.635) 13(-2.705,-1.905) 14(2.705,-1.905) 15(-2.705,-3.175) 16(2.705,-3.175) 17(-2.705,-4.445) 18(2.705,-4.445) 19(-2.705,-5.715) 20(2.705,-5.715)
  silkscreen extent -2.49,-6.35 2.49,6.7, body extent -3.76,-6.35 3.76,6.35, height 8.64
Samtec_TSM-105-02-x-SV [mm] "Header, 2.54mm, 5x1, SMT"
  rrect8% 1.27x3.43 smd: 1(-5.08,1.46) 2(-2.54,-1.46) 3(0,1.46) 4(2.54,-1.46) 5(5.08,1.46)
  body extent -6.35,-2.6 6.35,2.6, height 11.94
Samtec_TSW-102-23-X-S [mm] "Header, 2.54mm, 2x1, TH"
  rrect50% 1.53x1.53 hole 1.02: 1(-1.27,0)
  round 1.53 hole 1.02: 2(1.27,0)
  body extent -2.67,-1.27 2.54,1.27, height 8.38
Samtec_TSW-105-07-x-D [mm] "Header, 2.54mm, 5x2, TH"
  rect 1.55x1.55 hole 1.02: 1(-1.27,5.08)
  round 1.55 hole 1.02: 2(1.27,5.08) 3(-1.27,2.54) 4(1.27,2.54) 5(-1.27,0) 6(1.27,0) 7(-1.27,-2.54) 8(1.27,-2.54) 9(-1.27,-5.08) 10(1.27,-5.08)
  silkscreen extent -3,-6.35 2.54,6.35, body extent -2.54,-6.35 2.54,6.35, height 8.39
SER2915H [mm] "COILCRAFT"
  rect 5.59x5.33 smd: 1(-14.355,5.075) 2(-14.455,-5.075)
  rect 6.35x5.28 smd: 3(8.25,0)
  silkscreen extent -11.04,-14 10.81,13.9, body extent -16.7,-14.05 11.22,13.85, height 15.4
SOD-123 [mm] "On Semi recommended land pattern"
  rect 0.915x1.22 smd: 1(-1.637,0) 2(1.637,0)
  silkscreen extent -2.74,-1.17 2.03,1.17, body extent -1.93,-0.9 1.93,0.9, height 1.35
SOD-323 [mm] "NXP recommended land pattern"
  rect 0.6x0.6 smd paste-0.05: 1(-1.1,0) 2(1.1,0)
  silkscreen extent -2.06,-0.86 1.53,0.86, body extent -1.3,-0.67 1.3,0.68, height 1.1
TE_215307-3 [mm] "Receptacle, 2.54mm, 3x2, TH"
  rrect50% 1.35x1.35 hole 0.9: 1(-2.54,1.27)
  round 1.35 hole 0.9: 2(-2.54,-1.27) 3(0,1.27) 4(0,-1.27) 5(2.54,1.27) 6(2.54,-1.27)
  body extent -3.81,-2.53 3.81,2.53, height 7
TSW-105-07-X-S [mm] "Samtec 100mil, 1x5, 230 mil above insulator"
  rrect6% 1.65x1.65 hole 1.016: 1(-5.08,-0.025)
  round 1.65 hole 1.016: 2(-2.54,0) 3(0,0) 4(2.54,0) 5(5.08,0)
  silkscreen extent -7.05,-1.25 6.37,1.25, body extent -6.35,-1.27 6.35,1.27, height 8.38
WE-CMBNC_XL [mm] "TH, 4-Leads, Body 37x23mm"
  rect 3.1x3.1 hole 2.6: 1(-7.5,12.5)
  round 3.1 hole 2.6: 2(-7.5,-12.5) 3(7.5,-12.5) 4(7.5,12.5)
  silkscreen extent -10.3,-16.17 10.3,16.17, body extent -10.3,-16.17 10.3,16.17, height 30.09
WL-SMCW_RED_0805 [mm] "SMD, 2-Leads, Body 1.6x0.8mm"
  rect 1.1x1.2 smd: 1(-1.05,0) 2(1.05,0)
  silkscreen extent -2.4,-1.1 1.5,1.1, body extent -1,-0.62 1,0.63, height 0.7
Wurth_760390013 [mil] "Wurth"
  rect 44x38 smd: 1(-180,100) 2(-180,0) 3(-180,-100) 4(180,-100) 5(180,0) 6(180,100)
  silkscreen extent -190,-132 85,145, body extent -198,-135 198,130, height 166
Wurth_691311500102 [mm] "Terminal Block, 2 Pos, 5.08mm, TH"
  rrect50% 2.4x2.4 hole 1.6: 1(-2.54,0)
  round 2.4 hole 1.6: 2(2.54,0)
  body extent -6.08,-3.8 6.08,4.7, height 12

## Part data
C1 C4 C49 C50 C53 C61 C63 C69 C70: library part CMP-0007469-4, "CAP, CERM, 0.1 uF, 100 V, +/- 10%, X7R, 0603", Cap_Case=0603, Manufacturer=MuRata, Supplier Part Number 1=490-3285-1-ND, TempCo=X7R, Tolerance_%=10%, Value1=Unknown, Value2=100V, ValueDisplayed=0.1uF
C2 C11: "CAP, CERM, 1 µF, 25 V, +/- 10%, X7R, 0603", Cap_Case=0603, Manufacturer=MuRata, Supplier Part Number 1=490-5307-1-ND, TempCo=X7R, Tolerance_%=10, Value1=Unknown, Value2=25V, ValueDisplayed=1µF
C3 C41 C42: library part CMP-0007474-4, "CAP, CERM, 220 pF, 100 V, +/- 10%, X7R, 0603", Cap_Case=0603, Manufacturer=MuRata, Supplier Part Number 1=490-1460-1-ND, TempCo=X7R, Tolerance_%=10%, Value1=Unknown, Value2=100V, ValueDisplayed=220pF
C5 C10: "CAP, CERM, 2200 pF, 300 V, +/- 20%, E, TH, 2- Leads, Body 9x7mm, Pin Spacing 7.5mm", Cap_Case=9x7x9mm, Manufacturer=MuRata, Supplier Part Number 1=DE6E3KJ222MN3A-ND, TempCo=E, Tolerance_%=20, Value1=Unknown, Value2=300V, ValueDisplayed=2200pF
C6 C7 C12 C13: "CAP, CERM, 100 pF, 50 V,+/- 5%, C0G/NP0, 0603", Cap_Case=0603, Manufacturer=AVX, Supplier Part Number 1=478-1175-1-ND, TempCo=C0G/NP0, Tolerance_%=5, Value1="0.119 ohm", Value2=50V, ValueDisplayed=100pF
C8: library part CMP-0012561-1, "CAP, Film, 0.01 uF, 630 V, +/- 5%, AEC-Q200 Grade 2, TH", Cap_Case=18x5x11mm, Manufacturer=Kemet, Supplier Part Number 1=399-12529-ND, Tolerance_%=5%, Value1=Unknown, Value2=630V, ValueDisplayed=0.01uF
C9: library part CMP-0012443-3, "CAP, Film, 10 uF, 630 V, +/- 10%, TH", Manufacturer=TDK, Supplier Part Number 1=1815133, Tolerance_%=10%, Value1=Unknown, Value2=630V, ValueDisplayed=10uF
C14 C15 C28 C29 C30 C86: library part CMP-0081639-1, "CAP, CERM, 10 µF, 35 V,+/- 10%, X7R, 1210", Cap_Case=1210, Manufacturer=MuRata, Supplier Part Number 1=GRM32ER7YA106KA12K-ND, TempCo=X7R, Tolerance_%=10%, Value1="0.001 ohm", Value2=35V, ValueDisplayed=10µF
C16 C17 C18 C19 C20 C21 C22 C23 C31 C32 C33 C34 C35 C36 C37 C38: library part CMP-0008490-2, "CAP, CERM, 1500 pF, 100 V, +/- 10%, X7R, 1206", Cap_Case=1206, Manufacturer=AVX, Supplier Part Number 1=478-1518-1-ND, TempCo=X7R, Tolerance_%=10%, Value1="0.338 ohm", Value2=100V, ValueDisplayed=1500pF
C24 C25 C26 C27 C44 C71 C72: library part CMP-0010314-2, "CAP, AL, 390 uF, 35 V, +/- 20%, 0.055 ohm, AEC-Q200 Grade 1, TH", Cap_Case=12.5x20mm, Manufacturer=TDK, Supplier Part Number 1=B41896C7397M-ND, Tolerance_%=20%, Value1="0.055 ohm", Value2=35V, ValueDisplayed=390uF
C39 C40 C47 C56 C57 C58 C59: library part CMP-0007961-2, "CAP, CERM, 0.1 uF, 50 V, +/- 10%, X7R, AEC-Q200 Grade 1, 0805", Cap_Case=0805, Manufacturer=TDK, Supplier Part Number 1=445-7856-1-ND, TempCo=X7R, Tolerance_%=10%, Value1=Unknown, Value2=50V, ValueDisplayed=0.1uF
C43 C45 C48 C60 C62: library part CMP-0007995-2, "CAP, CERM, 10 uF, 16 V, +/- 10%, X7R, 0805", Cap_Case=0805, Manufacturer="Samsung Electro-Mechanics", TempCo=X7R, Tolerance_%=10%, Value1=Unknown, Value2=16V, ValueDisplayed=10uF
C46 C87 C88 C89: "CAP, CERM, 1 µF, 630 V,+/- 10%, X7R, AEC-Q200 Grade 1, 2220", Cap_Case=2220, Manufacturer="Knowles Capacitors", Supplier Part Number 1=1608-1181-1-ND, TempCo=X7R, Tolerance_%=10, Value2=630V, ValueDisplayed=1µF
C51: library part CMP-0008714-2, "CAP, CERM, 0.33 uF, 100 V, +/- 10%, X7R,", Cap_Case=1206_150, Manufacturer=TDK, Supplier Part Number 1=445-4464-1-ND, TempCo=X7R, Tolerance_%=10%, Value1="0.011504 ohm", Value2=100V, ValueDisplayed=0.33uF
